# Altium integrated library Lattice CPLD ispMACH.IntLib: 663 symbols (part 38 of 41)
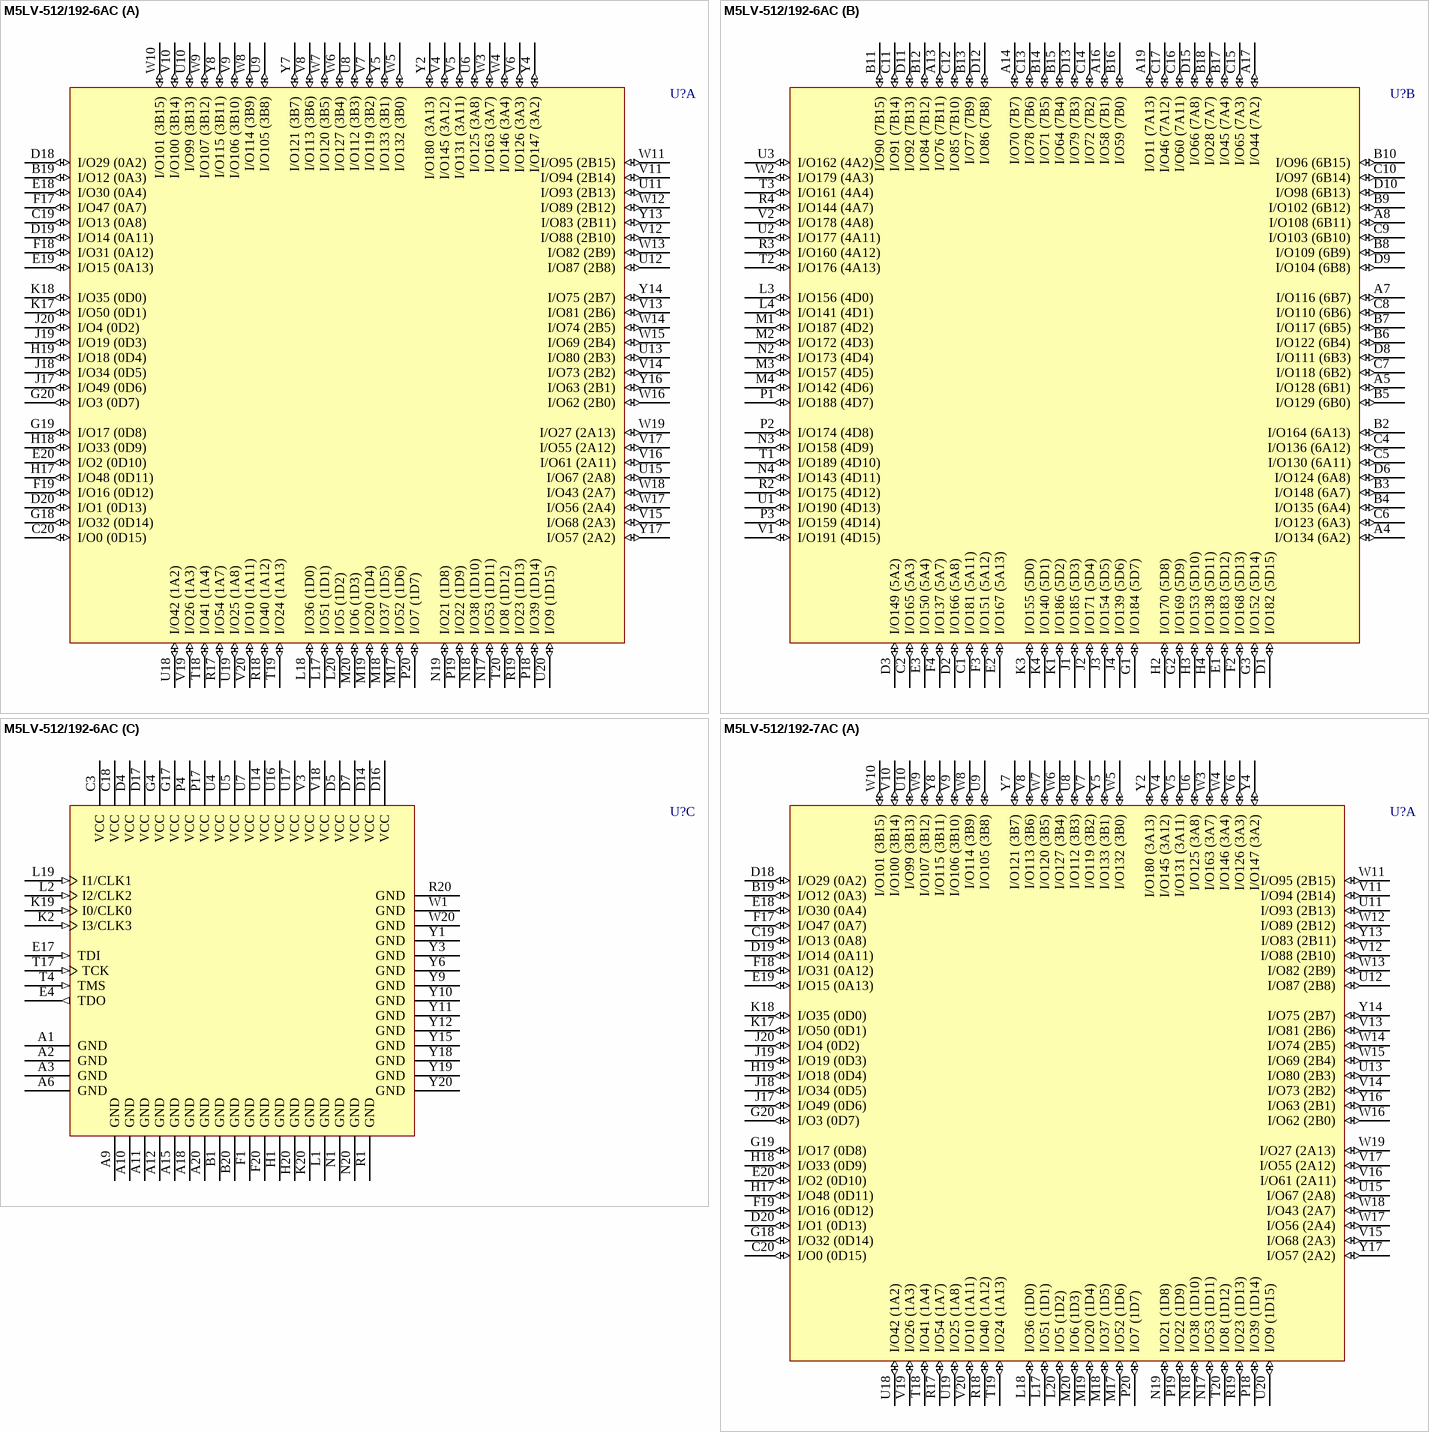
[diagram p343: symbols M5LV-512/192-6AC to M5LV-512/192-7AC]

## M5LV-512/192-6AC
designator U?
High-Density and High-I/O Complex PLD
footprint SBGA256 (BGA, 256-Leads, Body 27x27mm, Pitch 1.27mm)
3D model M5LV-SBGA256 (256-Ball Super Ball Grid Array (SBGA256))
part A pins: B19 I/O12 (0A3) (io), C19 I/O13 (0A8) (io), C20 I/O0 (0D15) (io), D18 I/O29 (0A2) (io), D19 I/O14 (0A11) (io), D20 I/O1 (0D13) (io), E18 I/O30 (0A4) (io), E19 I/O15 (0A13) (io), E20 I/O2 (0D10) (io), F17 I/O47 (0A7) (io), F18 I/O31 (0A12) (io), F19 I/O16 (0D12) (io), G18 I/O32 (0D14) (io), G19 I/O17 (0D8) (io), G20 I/O3 (0D7) (io), H17 I/O48 (0D11) (io), H18 I/O33 (0D9) (io), H19 I/O18 (0D4) (io), J17 I/O49 (0D6) (io), J18 I/O34 (0D5) (io), J19 I/O19 (0D3) (io), J20 I/O4 (0D2) (io), K17 I/O50 (0D1) (io), K18 I/O35 (0D0) (io), L17 I/O51 (1D1) (io), L18 I/O36 (1D0) (io), L20 I/O5 (1D2) (io), M17 I/O52 (1D6) (io), M18 I/O37 (1D5) (io), M19 I/O20 (1D4) (io), M20 I/O6 (1D3) (io), N17 I/O53 (1D11) (io), N18 I/O38 (1D10) (io), N19 I/O21 (1D8) (io), P18 I/O39 (1D14) (io), P19 I/O22 (1D9) (io), P20 I/O7 (1D7) (io), R17 I/O54 (1A7) (io), R18 I/O40 (1A12) (io), R19 I/O23 (1D13) (io), T18 I/O41 (1A4) (io), T19 I/O24 (1A13) (io), T20 I/O8 (1D12) (io), U6 I/O125 (3A8) (io), U8 I/O112 (3B3) (io), U9 I/O105 (3B8) (io), U10 I/O99 (3B13) (io), U11 I/O93 (2B13) (io), U12 I/O87 (2B8) (io), U13 I/O80 (2B3) (io), U15 I/O67 (2A8) (io), U18 I/O42 (1A2) (io), U19 I/O25 (1A8) (io), U20 I/O9 (1D15) (io), V4 I/O145 (3A12) (io), V5 I/O131 (3A11) (io), V6 I/O126 (3A3) (io), V7 I/O119 (3B2) (io), V8 I/O113 (3B6) (io), V9 I/O106 (3B10) (io), V10 I/O100 (3B14) (io), V11 I/O94 (2B14) (io), V12 I/O88 (2B10) (io), V13 I/O81 (2B6) (io), V14 I/O73 (2B2) (io), V15 I/O68 (2A3) (io), V16 I/O61 (2A11) (io), V17 I/O55 (2A12) (io), V19 I/O26 (1A3) (io), V20 I/O10 (1A11) (io), W3 I/O163 (3A7) (io), W4 I/O146 (3A4) (io), W5 I/O132 (3B0) (io), W6 I/O127 (3B4) (io), W7 I/O120 (3B5) (io), W8 I/O114 (3B9) (io), W9 I/O107 (3B12) (io), W10 I/O101 (3B15) (io), W11 I/O95 (2B15) (io), W12 I/O89 (2B12) (io), W13 I/O82 (2B9) (io), W14 I/O74 (2B5) (io), W15 I/O69 (2B4) (io), W16 I/O62 (2B0) (io), W17 I/O56 (2A4) (io), W18 I/O43 (2A7) (io), W19 I/O27 (2A13) (io), Y2 I/O180 (3A13) (io), Y4 I/O147 (3A2) (io), Y5 I/O133 (3B1) (io), Y7 I/O121 (3B7) (io), Y8 I/O115 (3B11) (io), Y13 I/O83 (2B11) (io), Y14 I/O75 (2B7) (io), Y16 I/O63 (2B1) (io), Y17 I/O57 (2A2) (io)
part B pins: A4 I/O134 (6A2) (io), A5 I/O128 (6B1) (io), A7 I/O116 (6B7) (io), A8 I/O108 (6B11) (io), A13 I/O76 (7B11) (io), A14 I/O70 (7B7) (io), A16 I/O58 (7B1) (io), A17 I/O44 (7A2) (io), A19 I/O11 (7A13) (io), B2 I/O164 (6A13) (io), B3 I/O148 (6A7) (io), B4 I/O135 (6A4) (io), B5 I/O129 (6B0) (io), B6 I/O122 (6B4) (io), B7 I/O117 (6B5) (io), B8 I/O109 (6B9) (io), B9 I/O102 (6B12) (io), B10 I/O96 (6B15) (io), B11 I/O90 (7B15) (io), B12 I/O84 (7B12) (io), B13 I/O77 (7B9) (io), B14 I/O71 (7B5) (io), B15 I/O64 (7B4) (io), B16 I/O59 (7B0) (io), B17 I/O45 (7A4) (io), B18 I/O28 (7A7) (io), C1 I/O181 (5A11) (io), C2 I/O165 (5A3) (io), C4 I/O136 (6A12) (io), C5 I/O130 (6A11) (io), C6 I/O123 (6A3) (io), C7 I/O118 (6B2) (io), C8 I/O110 (6B6) (io), C9 I/O103 (6B10) (io), C10 I/O97 (6B14) (io), C11 I/O91 (7B14) (io), C12 I/O85 (7B10) (io), C13 I/O78 (7B6) (io), C14 I/O72 (7B2) (io), C15 I/O65 (7A3) (io), C16 I/O60 (7A11) (io), C17 I/O46 (7A12) (io), D1 I/O182 (5D15) (io), D2 I/O166 (5A8) (io), D3 I/O149 (5A2) (io), D6 I/O124 (6A8) (io), D8 I/O111 (6B3) (io), D9 I/O104 (6B8) (io), D10 I/O98 (6B13) (io), D11 I/O92 (7B13) (io), D12 I/O86 (7B8) (io), D13 I/O79 (7B3) (io), D15 I/O66 (7A8) (io), E1 I/O183 (5D12) (io), E2 I/O167 (5A13) (io), E3 I/O150 (5A4) (io), F2 I/O168 (5D13) (io), F3 I/O151 (5A12) (io), F4 I/O137 (5A7) (io), G1 I/O184 (5D7) (io), G2 I/O169 (5D9) (io), G3 I/O152 (5D14) (io), H2 I/O170 (5D8) (io), H3 I/O153 (5D10) (io), H4 I/O138 (5D11) (io), J1 I/O185 (5D3) (io), J2 I/O171 (5D4) (io), J3 I/O154 (5D5) (io), J4 I/O139 (5D6) (io), K1 I/O186 (5D2) (io), K3 I/O155 (5D0) (io), K4 I/O140 (5D1) (io), L3 I/O156 (4D0) (io), L4 I/O141 (4D1) (io), M1 I/O187 (4D2) (io), M2 I/O172 (4D3) (io), M3 I/O157 (4D5) (io), M4 I/O142 (4D6) (io), N2 I/O173 (4D4) (io), N3 I/O158 (4D9) (io), N4 I/O143 (4D11) (io), P1 I/O188 (4D7) (io), P2 I/O174 (4D8) (io), P3 I/O159 (4D14) (io), R2 I/O175 (4D12) (io), R3 I/O160 (4A12) (io), R4 I/O144 (4A7) (io), T1 I/O189 (4D10) (io), T2 I/O176 (4A13) (io), T3 I/O161 (4A4) (io), U1 I/O190 (4D13) (io), U2 I/O177 (4A11) (io), U3 I/O162 (4A2) (io), V1 I/O191 (4D15) (io), V2 I/O178 (4A8) (io), W2 I/O179 (4A3) (io)
part C pins: A1 GND (power), A2 GND (power), A3 GND (power), A6 GND (power), A9 GND (power), A10 GND (power), A11 GND (power), A12 GND (power), A15 GND (power), A18 GND (power), A20 GND (power), B1 GND (power), B20 GND (power), C3 VCC (power), C18 VCC (power), D4 VCC (power), D5 VCC (power), D7 VCC (power), D14 VCC (power), D16 VCC (power), D17 VCC (power), E4 TDO (out), E17 TDI (in), F1 GND (power), F20 GND (power), G4 VCC (power), G17 VCC (power), H1 GND (power), H20 GND (power), K2 I3/CLK3 (in), K19 I0/CLK0 (in), K20 GND (power), L1 GND (power), L2 I2/CLK2 (in), L19 I1/CLK1 (in), N1 GND (power), N20 GND (power), P4 VCC (power), P17 VCC (power), R1 GND (power), R20 GND (power), T4 TMS (in), T17 TCK (in), U4 VCC (power), U5 VCC (power), U7 VCC (power), U14 VCC (power), U16 VCC (power), U17 VCC (power), V3 VCC (power), V18 VCC (power), W1 GND (power), W20 GND (power), Y1 GND (power), Y3 GND (power), Y6 GND (power), Y9 GND (power), Y10 GND (power), Y11 GND (power), Y12 GND (power), Y15 GND (power), Y18 GND (power), Y19 GND (power), Y20 GND (power)

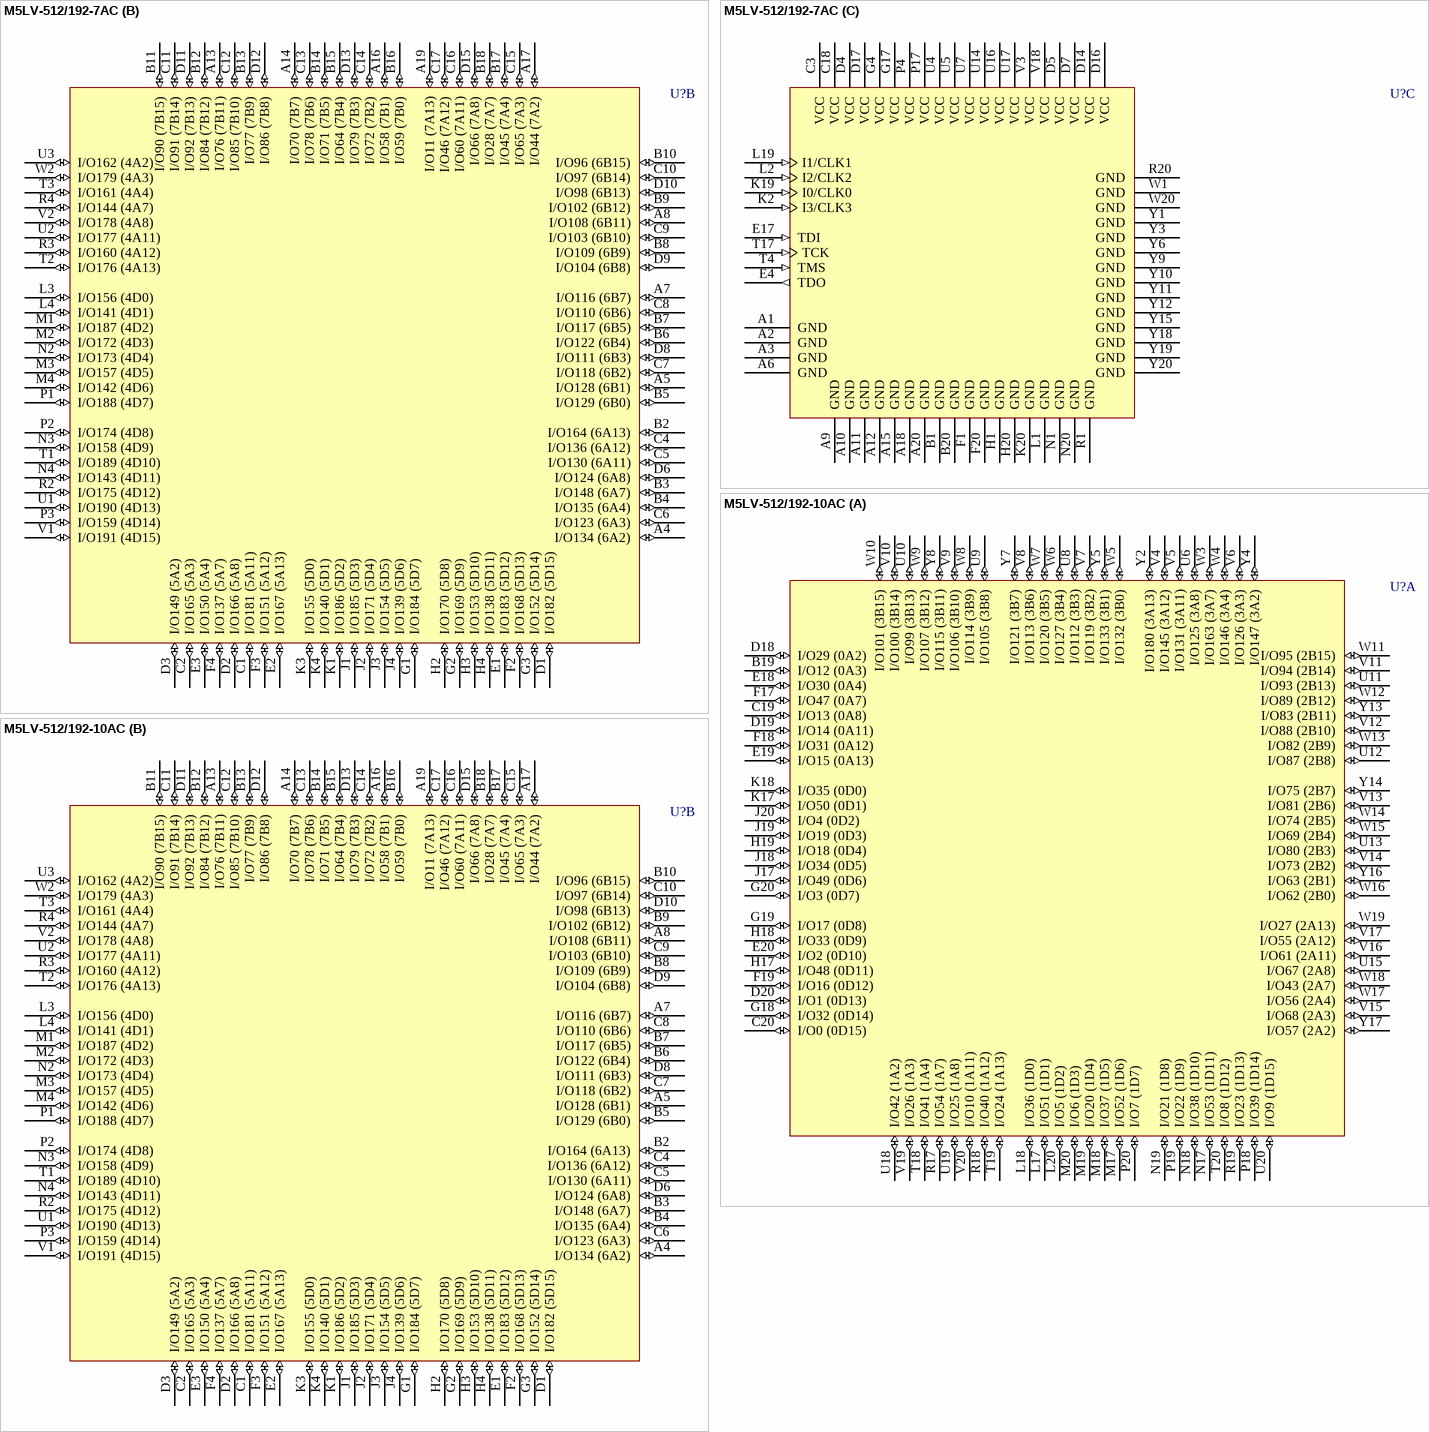
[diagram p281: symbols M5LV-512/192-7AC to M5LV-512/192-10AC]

## M5LV-512/192-7AC
designator U?
High-Density and High-I/O Complex PLD
footprint SBGA256 (BGA, 256-Leads, Body 27x27mm, Pitch 1.27mm)
3D model M5LV-SBGA256 (256-Ball Super Ball Grid Array (SBGA256))
part A pins: B19 I/O12 (0A3) (io), C19 I/O13 (0A8) (io), C20 I/O0 (0D15) (io), D18 I/O29 (0A2) (io), D19 I/O14 (0A11) (io), D20 I/O1 (0D13) (io), E18 I/O30 (0A4) (io), E19 I/O15 (0A13) (io), E20 I/O2 (0D10) (io), F17 I/O47 (0A7) (io), F18 I/O31 (0A12) (io), F19 I/O16 (0D12) (io), G18 I/O32 (0D14) (io), G19 I/O17 (0D8) (io), G20 I/O3 (0D7) (io), H17 I/O48 (0D11) (io), H18 I/O33 (0D9) (io), H19 I/O18 (0D4) (io), J17 I/O49 (0D6) (io), J18 I/O34 (0D5) (io), J19 I/O19 (0D3) (io), J20 I/O4 (0D2) (io), K17 I/O50 (0D1) (io), K18 I/O35 (0D0) (io), L17 I/O51 (1D1) (io), L18 I/O36 (1D0) (io), L20 I/O5 (1D2) (io), M17 I/O52 (1D6) (io), M18 I/O37 (1D5) (io), M19 I/O20 (1D4) (io), M20 I/O6 (1D3) (io), N17 I/O53 (1D11) (io), N18 I/O38 (1D10) (io), N19 I/O21 (1D8) (io), P18 I/O39 (1D14) (io), P19 I/O22 (1D9) (io), P20 I/O7 (1D7) (io), R17 I/O54 (1A7) (io), R18 I/O40 (1A12) (io), R19 I/O23 (1D13) (io), T18 I/O41 (1A4) (io), T19 I/O24 (1A13) (io), T20 I/O8 (1D12) (io), U6 I/O125 (3A8) (io), U8 I/O112 (3B3) (io), U9 I/O105 (3B8) (io), U10 I/O99 (3B13) (io), U11 I/O93 (2B13) (io), U12 I/O87 (2B8) (io), U13 I/O80 (2B3) (io), U15 I/O67 (2A8) (io), U18 I/O42 (1A2) (io), U19 I/O25 (1A8) (io), U20 I/O9 (1D15) (io), V4 I/O145 (3A12) (io), V5 I/O131 (3A11) (io), V6 I/O126 (3A3) (io), V7 I/O119 (3B2) (io), V8 I/O113 (3B6) (io), V9 I/O106 (3B10) (io), V10 I/O100 (3B14) (io), V11 I/O94 (2B14) (io), V12 I/O88 (2B10) (io), V13 I/O81 (2B6) (io), V14 I/O73 (2B2) (io), V15 I/O68 (2A3) (io), V16 I/O61 (2A11) (io), V17 I/O55 (2A12) (io), V19 I/O26 (1A3) (io), V20 I/O10 (1A11) (io), W3 I/O163 (3A7) (io), W4 I/O146 (3A4) (io), W5 I/O132 (3B0) (io), W6 I/O127 (3B4) (io), W7 I/O120 (3B5) (io), W8 I/O114 (3B9) (io), W9 I/O107 (3B12) (io), W10 I/O101 (3B15) (io), W11 I/O95 (2B15) (io), W12 I/O89 (2B12) (io), W13 I/O82 (2B9) (io), W14 I/O74 (2B5) (io), W15 I/O69 (2B4) (io), W16 I/O62 (2B0) (io), W17 I/O56 (2A4) (io), W18 I/O43 (2A7) (io), W19 I/O27 (2A13) (io), Y2 I/O180 (3A13) (io), Y4 I/O147 (3A2) (io), Y5 I/O133 (3B1) (io), Y7 I/O121 (3B7) (io), Y8 I/O115 (3B11) (io), Y13 I/O83 (2B11) (io), Y14 I/O75 (2B7) (io), Y16 I/O63 (2B1) (io), Y17 I/O57 (2A2) (io)
part B pins: A4 I/O134 (6A2) (io), A5 I/O128 (6B1) (io), A7 I/O116 (6B7) (io), A8 I/O108 (6B11) (io), A13 I/O76 (7B11) (io), A14 I/O70 (7B7) (io), A16 I/O58 (7B1) (io), A17 I/O44 (7A2) (io), A19 I/O11 (7A13) (io), B2 I/O164 (6A13) (io), B3 I/O148 (6A7) (io), B4 I/O135 (6A4) (io), B5 I/O129 (6B0) (io), B6 I/O122 (6B4) (io), B7 I/O117 (6B5) (io), B8 I/O109 (6B9) (io), B9 I/O102 (6B12) (io), B10 I/O96 (6B15) (io), B11 I/O90 (7B15) (io), B12 I/O84 (7B12) (io), B13 I/O77 (7B9) (io), B14 I/O71 (7B5) (io), B15 I/O64 (7B4) (io), B16 I/O59 (7B0) (io), B17 I/O45 (7A4) (io), B18 I/O28 (7A7) (io), C1 I/O181 (5A11) (io), C2 I/O165 (5A3) (io), C4 I/O136 (6A12) (io), C5 I/O130 (6A11) (io), C6 I/O123 (6A3) (io), C7 I/O118 (6B2) (io), C8 I/O110 (6B6) (io), C9 I/O103 (6B10) (io), C10 I/O97 (6B14) (io), C11 I/O91 (7B14) (io), C12 I/O85 (7B10) (io), C13 I/O78 (7B6) (io), C14 I/O72 (7B2) (io), C15 I/O65 (7A3) (io), C16 I/O60 (7A11) (io), C17 I/O46 (7A12) (io), D1 I/O182 (5D15) (io), D2 I/O166 (5A8) (io), D3 I/O149 (5A2) (io), D6 I/O124 (6A8) (io), D8 I/O111 (6B3) (io), D9 I/O104 (6B8) (io), D10 I/O98 (6B13) (io), D11 I/O92 (7B13) (io), D12 I/O86 (7B8) (io), D13 I/O79 (7B3) (io), D15 I/O66 (7A8) (io), E1 I/O183 (5D12) (io), E2 I/O167 (5A13) (io), E3 I/O150 (5A4) (io), F2 I/O168 (5D13) (io), F3 I/O151 (5A12) (io), F4 I/O137 (5A7) (io), G1 I/O184 (5D7) (io), G2 I/O169 (5D9) (io), G3 I/O152 (5D14) (io), H2 I/O170 (5D8) (io), H3 I/O153 (5D10) (io), H4 I/O138 (5D11) (io), J1 I/O185 (5D3) (io), J2 I/O171 (5D4) (io), J3 I/O154 (5D5) (io), J4 I/O139 (5D6) (io), K1 I/O186 (5D2) (io), K3 I/O155 (5D0) (io), K4 I/O140 (5D1) (io), L3 I/O156 (4D0) (io), L4 I/O141 (4D1) (io), M1 I/O187 (4D2) (io), M2 I/O172 (4D3) (io), M3 I/O157 (4D5) (io), M4 I/O142 (4D6) (io), N2 I/O173 (4D4) (io), N3 I/O158 (4D9) (io), N4 I/O143 (4D11) (io), P1 I/O188 (4D7) (io), P2 I/O174 (4D8) (io), P3 I/O159 (4D14) (io), R2 I/O175 (4D12) (io), R3 I/O160 (4A12) (io), R4 I/O144 (4A7) (io), T1 I/O189 (4D10) (io), T2 I/O176 (4A13) (io), T3 I/O161 (4A4) (io), U1 I/O190 (4D13) (io), U2 I/O177 (4A11) (io), U3 I/O162 (4A2) (io), V1 I/O191 (4D15) (io), V2 I/O178 (4A8) (io), W2 I/O179 (4A3) (io)
part C pins: A1 GND (power), A2 GND (power), A3 GND (power), A6 GND (power), A9 GND (power), A10 GND (power), A11 GND (power), A12 GND (power), A15 GND (power), A18 GND (power), A20 GND (power), B1 GND (power), B20 GND (power), C3 VCC (power), C18 VCC (power), D4 VCC (power), D5 VCC (power), D7 VCC (power), D14 VCC (power), D16 VCC (power), D17 VCC (power), E4 TDO (out), E17 TDI (in), F1 GND (power), F20 GND (power), G4 VCC (power), G17 VCC (power), H1 GND (power), H20 GND (power), K2 I3/CLK3 (in), K19 I0/CLK0 (in), K20 GND (power), L1 GND (power), L2 I2/CLK2 (in), L19 I1/CLK1 (in), N1 GND (power), N20 GND (power), P4 VCC (power), P17 VCC (power), R1 GND (power), R20 GND (power), T4 TMS (in), T17 TCK (in), U4 VCC (power), U5 VCC (power), U7 VCC (power), U14 VCC (power), U16 VCC (power), U17 VCC (power), V3 VCC (power), V18 VCC (power), W1 GND (power), W20 GND (power), Y1 GND (power), Y3 GND (power), Y6 GND (power), Y9 GND (power), Y10 GND (power), Y11 GND (power), Y12 GND (power), Y15 GND (power), Y18 GND (power), Y19 GND (power), Y20 GND (power)

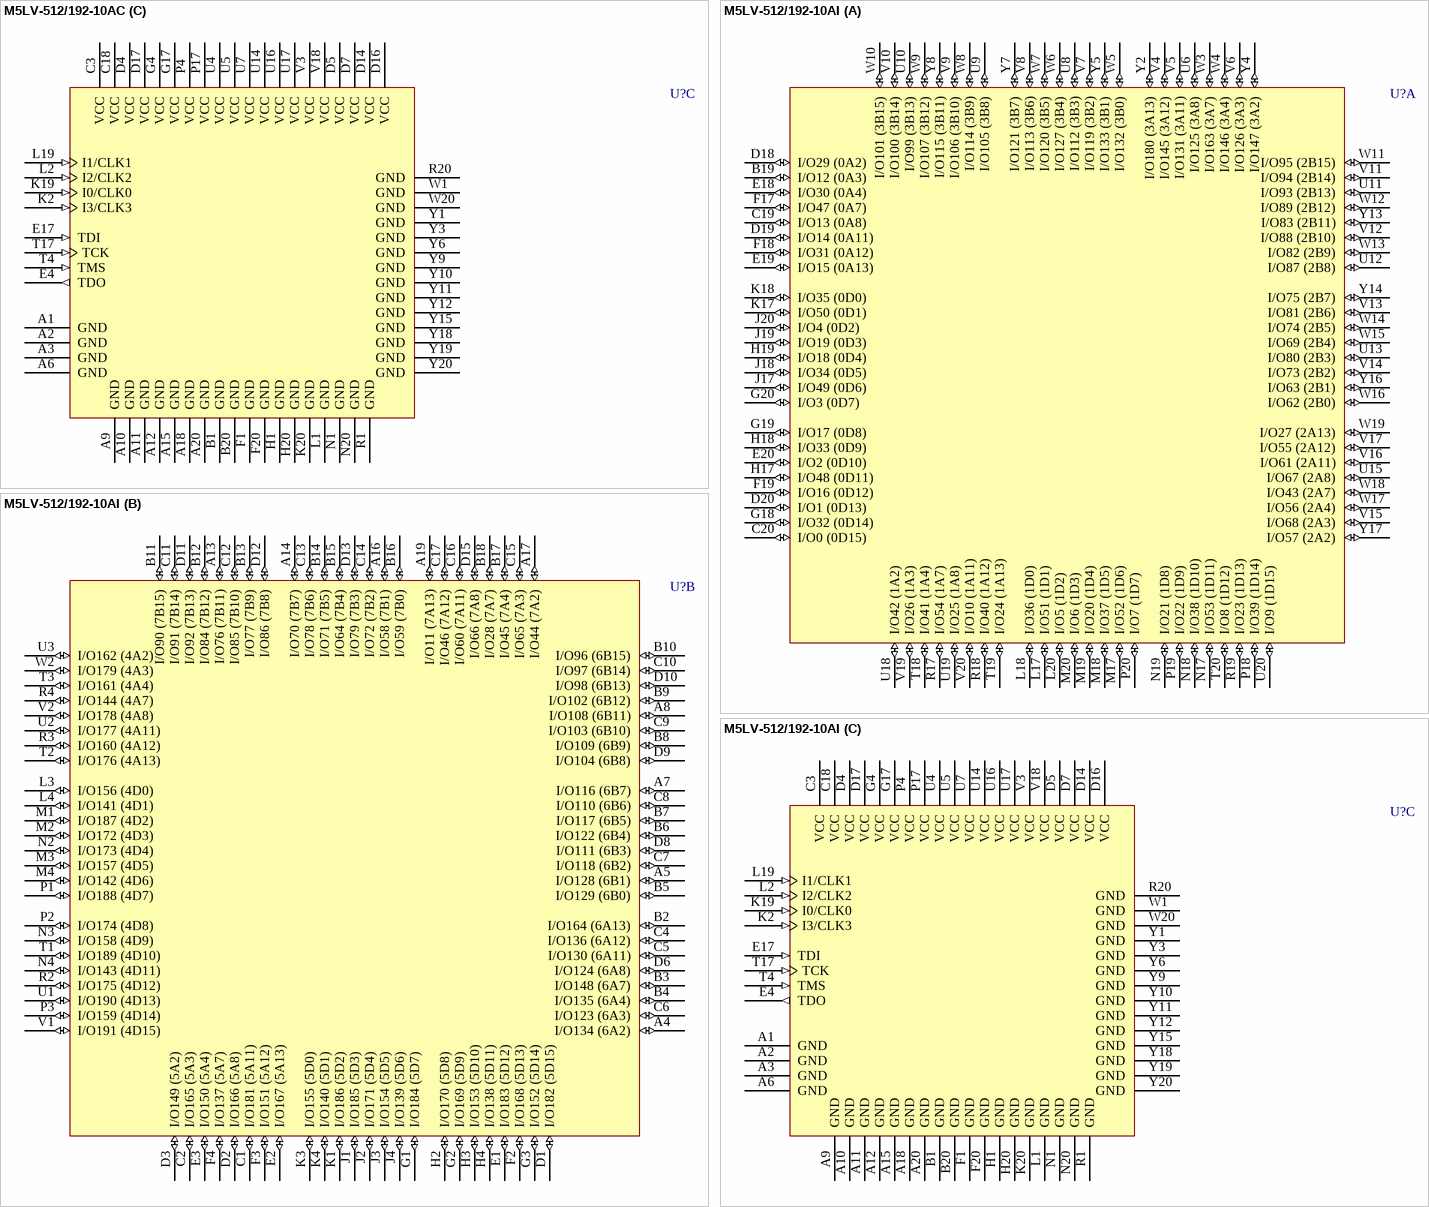
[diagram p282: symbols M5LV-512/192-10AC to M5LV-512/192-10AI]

## M5LV-512/192-10AC
designator U?
High-Density and High-I/O Complex PLD
footprint SBGA256 (BGA, 256-Leads, Body 27x27mm, Pitch 1.27mm)
3D model M5LV-SBGA256 (256-Ball Super Ball Grid Array (SBGA256))
part A pins: B19 I/O12 (0A3) (io), C19 I/O13 (0A8) (io), C20 I/O0 (0D15) (io), D18 I/O29 (0A2) (io), D19 I/O14 (0A11) (io), D20 I/O1 (0D13) (io), E18 I/O30 (0A4) (io), E19 I/O15 (0A13) (io), E20 I/O2 (0D10) (io), F17 I/O47 (0A7) (io), F18 I/O31 (0A12) (io), F19 I/O16 (0D12) (io), G18 I/O32 (0D14) (io), G19 I/O17 (0D8) (io), G20 I/O3 (0D7) (io), H17 I/O48 (0D11) (io), H18 I/O33 (0D9) (io), H19 I/O18 (0D4) (io), J17 I/O49 (0D6) (io), J18 I/O34 (0D5) (io), J19 I/O19 (0D3) (io), J20 I/O4 (0D2) (io), K17 I/O50 (0D1) (io), K18 I/O35 (0D0) (io), L17 I/O51 (1D1) (io), L18 I/O36 (1D0) (io), L20 I/O5 (1D2) (io), M17 I/O52 (1D6) (io), M18 I/O37 (1D5) (io), M19 I/O20 (1D4) (io), M20 I/O6 (1D3) (io), N17 I/O53 (1D11) (io), N18 I/O38 (1D10) (io), N19 I/O21 (1D8) (io), P18 I/O39 (1D14) (io), P19 I/O22 (1D9) (io), P20 I/O7 (1D7) (io), R17 I/O54 (1A7) (io), R18 I/O40 (1A12) (io), R19 I/O23 (1D13) (io), T18 I/O41 (1A4) (io), T19 I/O24 (1A13) (io), T20 I/O8 (1D12) (io), U6 I/O125 (3A8) (io), U8 I/O112 (3B3) (io), U9 I/O105 (3B8) (io), U10 I/O99 (3B13) (io), U11 I/O93 (2B13) (io), U12 I/O87 (2B8) (io), U13 I/O80 (2B3) (io), U15 I/O67 (2A8) (io), U18 I/O42 (1A2) (io), U19 I/O25 (1A8) (io), U20 I/O9 (1D15) (io), V4 I/O145 (3A12) (io), V5 I/O131 (3A11) (io), V6 I/O126 (3A3) (io), V7 I/O119 (3B2) (io), V8 I/O113 (3B6) (io), V9 I/O106 (3B10) (io), V10 I/O100 (3B14) (io), V11 I/O94 (2B14) (io), V12 I/O88 (2B10) (io), V13 I/O81 (2B6) (io), V14 I/O73 (2B2) (io), V15 I/O68 (2A3) (io), V16 I/O61 (2A11) (io), V17 I/O55 (2A12) (io), V19 I/O26 (1A3) (io), V20 I/O10 (1A11) (io), W3 I/O163 (3A7) (io), W4 I/O146 (3A4) (io), W5 I/O132 (3B0) (io), W6 I/O127 (3B4) (io), W7 I/O120 (3B5) (io), W8 I/O114 (3B9) (io), W9 I/O107 (3B12) (io), W10 I/O101 (3B15) (io), W11 I/O95 (2B15) (io), W12 I/O89 (2B12) (io), W13 I/O82 (2B9) (io), W14 I/O74 (2B5) (io), W15 I/O69 (2B4) (io), W16 I/O62 (2B0) (io), W17 I/O56 (2A4) (io), W18 I/O43 (2A7) (io), W19 I/O27 (2A13) (io), Y2 I/O180 (3A13) (io), Y4 I/O147 (3A2) (io), Y5 I/O133 (3B1) (io), Y7 I/O121 (3B7) (io), Y8 I/O115 (3B11) (io), Y13 I/O83 (2B11) (io), Y14 I/O75 (2B7) (io), Y16 I/O63 (2B1) (io), Y17 I/O57 (2A2) (io)
part B pins: A4 I/O134 (6A2) (io), A5 I/O128 (6B1) (io), A7 I/O116 (6B7) (io), A8 I/O108 (6B11) (io), A13 I/O76 (7B11) (io), A14 I/O70 (7B7) (io), A16 I/O58 (7B1) (io), A17 I/O44 (7A2) (io), A19 I/O11 (7A13) (io), B2 I/O164 (6A13) (io), B3 I/O148 (6A7) (io), B4 I/O135 (6A4) (io), B5 I/O129 (6B0) (io), B6 I/O122 (6B4) (io), B7 I/O117 (6B5) (io), B8 I/O109 (6B9) (io), B9 I/O102 (6B12) (io), B10 I/O96 (6B15) (io), B11 I/O90 (7B15) (io), B12 I/O84 (7B12) (io), B13 I/O77 (7B9) (io), B14 I/O71 (7B5) (io), B15 I/O64 (7B4) (io), B16 I/O59 (7B0) (io), B17 I/O45 (7A4) (io), B18 I/O28 (7A7) (io), C1 I/O181 (5A11) (io), C2 I/O165 (5A3) (io), C4 I/O136 (6A12) (io), C5 I/O130 (6A11) (io), C6 I/O123 (6A3) (io), C7 I/O118 (6B2) (io), C8 I/O110 (6B6) (io), C9 I/O103 (6B10) (io), C10 I/O97 (6B14) (io), C11 I/O91 (7B14) (io), C12 I/O85 (7B10) (io), C13 I/O78 (7B6) (io), C14 I/O72 (7B2) (io), C15 I/O65 (7A3) (io), C16 I/O60 (7A11) (io), C17 I/O46 (7A12) (io), D1 I/O182 (5D15) (io), D2 I/O166 (5A8) (io), D3 I/O149 (5A2) (io), D6 I/O124 (6A8) (io), D8 I/O111 (6B3) (io), D9 I/O104 (6B8) (io), D10 I/O98 (6B13) (io), D11 I/O92 (7B13) (io), D12 I/O86 (7B8) (io), D13 I/O79 (7B3) (io), D15 I/O66 (7A8) (io), E1 I/O183 (5D12) (io), E2 I/O167 (5A13) (io), E3 I/O150 (5A4) (io), F2 I/O168 (5D13) (io), F3 I/O151 (5A12) (io), F4 I/O137 (5A7) (io), G1 I/O184 (5D7) (io), G2 I/O169 (5D9) (io), G3 I/O152 (5D14) (io), H2 I/O170 (5D8) (io), H3 I/O153 (5D10) (io), H4 I/O138 (5D11) (io), J1 I/O185 (5D3) (io), J2 I/O171 (5D4) (io), J3 I/O154 (5D5) (io), J4 I/O139 (5D6) (io), K1 I/O186 (5D2) (io), K3 I/O155 (5D0) (io), K4 I/O140 (5D1) (io), L3 I/O156 (4D0) (io), L4 I/O141 (4D1) (io), M1 I/O187 (4D2) (io), M2 I/O172 (4D3) (io), M3 I/O157 (4D5) (io), M4 I/O142 (4D6) (io), N2 I/O173 (4D4) (io), N3 I/O158 (4D9) (io), N4 I/O143 (4D11) (io), P1 I/O188 (4D7) (io), P2 I/O174 (4D8) (io), P3 I/O159 (4D14) (io), R2 I/O175 (4D12) (io), R3 I/O160 (4A12) (io), R4 I/O144 (4A7) (io), T1 I/O189 (4D10) (io), T2 I/O176 (4A13) (io), T3 I/O161 (4A4) (io), U1 I/O190 (4D13) (io), U2 I/O177 (4A11) (io), U3 I/O162 (4A2) (io), V1 I/O191 (4D15) (io), V2 I/O178 (4A8) (io), W2 I/O179 (4A3) (io)
part C pins: A1 GND (power), A2 GND (power), A3 GND (power), A6 GND (power), A9 GND (power), A10 GND (power), A11 GND (power), A12 GND (power), A15 GND (power), A18 GND (power), A20 GND (power), B1 GND (power), B20 GND (power), C3 VCC (power), C18 VCC (power), D4 VCC (power), D5 VCC (power), D7 VCC (power), D14 VCC (power), D16 VCC (power), D17 VCC (power), E4 TDO (out), E17 TDI (in), F1 GND (power), F20 GND (power), G4 VCC (power), G17 VCC (power), H1 GND (power), H20 GND (power), K2 I3/CLK3 (in), K19 I0/CLK0 (in), K20 GND (power), L1 GND (power), L2 I2/CLK2 (in), L19 I1/CLK1 (in), N1 GND (power), N20 GND (power), P4 VCC (power), P17 VCC (power), R1 GND (power), R20 GND (power), T4 TMS (in), T17 TCK (in), U4 VCC (power), U5 VCC (power), U7 VCC (power), U14 VCC (power), U16 VCC (power), U17 VCC (power), V3 VCC (power), V18 VCC (power), W1 GND (power), W20 GND (power), Y1 GND (power), Y3 GND (power), Y6 GND (power), Y9 GND (power), Y10 GND (power), Y11 GND (power), Y12 GND (power), Y15 GND (power), Y18 GND (power), Y19 GND (power), Y20 GND (power)

## M5LV-512/192-10AI
designator U?
High-Density and High-I/O Complex PLD
footprint SBGA256 (BGA, 256-Leads, Body 27x27mm, Pitch 1.27mm)
3D model M5LV-SBGA256 (256-Ball Super Ball Grid Array (SBGA256))
part A pins: B19 I/O12 (0A3) (io), C19 I/O13 (0A8) (io), C20 I/O0 (0D15) (io), D18 I/O29 (0A2) (io), D19 I/O14 (0A11) (io), D20 I/O1 (0D13) (io), E18 I/O30 (0A4) (io), E19 I/O15 (0A13) (io), E20 I/O2 (0D10) (io), F17 I/O47 (0A7) (io), F18 I/O31 (0A12) (io), F19 I/O16 (0D12) (io), G18 I/O32 (0D14) (io), G19 I/O17 (0D8) (io), G20 I/O3 (0D7) (io), H17 I/O48 (0D11) (io), H18 I/O33 (0D9) (io), H19 I/O18 (0D4) (io), J17 I/O49 (0D6) (io), J18 I/O34 (0D5) (io), J19 I/O19 (0D3) (io), J20 I/O4 (0D2) (io), K17 I/O50 (0D1) (io), K18 I/O35 (0D0) (io), L17 I/O51 (1D1) (io), L18 I/O36 (1D0) (io), L20 I/O5 (1D2) (io), M17 I/O52 (1D6) (io), M18 I/O37 (1D5) (io), M19 I/O20 (1D4) (io), M20 I/O6 (1D3) (io), N17 I/O53 (1D11) (io), N18 I/O38 (1D10) (io), N19 I/O21 (1D8) (io), P18 I/O39 (1D14) (io), P19 I/O22 (1D9) (io), P20 I/O7 (1D7) (io), R17 I/O54 (1A7) (io), R18 I/O40 (1A12) (io), R19 I/O23 (1D13) (io), T18 I/O41 (1A4) (io), T19 I/O24 (1A13) (io), T20 I/O8 (1D12) (io), U6 I/O125 (3A8) (io), U8 I/O112 (3B3) (io), U9 I/O105 (3B8) (io), U10 I/O99 (3B13) (io), U11 I/O93 (2B13) (io), U12 I/O87 (2B8) (io), U13 I/O80 (2B3) (io), U15 I/O67 (2A8) (io), U18 I/O42 (1A2) (io), U19 I/O25 (1A8) (io), U20 I/O9 (1D15) (io), V4 I/O145 (3A12) (io), V5 I/O131 (3A11) (io), V6 I/O126 (3A3) (io), V7 I/O119 (3B2) (io), V8 I/O113 (3B6) (io), V9 I/O106 (3B10) (io), V10 I/O100 (3B14) (io), V11 I/O94 (2B14) (io), V12 I/O88 (2B10) (io), V13 I/O81 (2B6) (io), V14 I/O73 (2B2) (io), V15 I/O68 (2A3) (io), V16 I/O61 (2A11) (io), V17 I/O55 (2A12) (io), V19 I/O26 (1A3) (io), V20 I/O10 (1A11) (io), W3 I/O163 (3A7) (io), W4 I/O146 (3A4) (io), W5 I/O132 (3B0) (io), W6 I/O127 (3B4) (io), W7 I/O120 (3B5) (io), W8 I/O114 (3B9) (io), W9 I/O107 (3B12) (io), W10 I/O101 (3B15) (io), W11 I/O95 (2B15) (io), W12 I/O89 (2B12) (io), W13 I/O82 (2B9) (io), W14 I/O74 (2B5) (io), W15 I/O69 (2B4) (io), W16 I/O62 (2B0) (io), W17 I/O56 (2A4) (io), W18 I/O43 (2A7) (io), W19 I/O27 (2A13) (io), Y2 I/O180 (3A13) (io), Y4 I/O147 (3A2) (io), Y5 I/O133 (3B1) (io), Y7 I/O121 (3B7) (io), Y8 I/O115 (3B11) (io), Y13 I/O83 (2B11) (io), Y14 I/O75 (2B7) (io), Y16 I/O63 (2B1) (io), Y17 I/O57 (2A2) (io)
part B pins: A4 I/O134 (6A2) (io), A5 I/O128 (6B1) (io), A7 I/O116 (6B7) (io), A8 I/O108 (6B11) (io), A13 I/O76 (7B11) (io), A14 I/O70 (7B7) (io), A16 I/O58 (7B1) (io), A17 I/O44 (7A2) (io), A19 I/O11 (7A13) (io), B2 I/O164 (6A13) (io), B3 I/O148 (6A7) (io), B4 I/O135 (6A4) (io), B5 I/O129 (6B0) (io), B6 I/O122 (6B4) (io), B7 I/O117 (6B5) (io), B8 I/O109 (6B9) (io), B9 I/O102 (6B12) (io), B10 I/O96 (6B15) (io), B11 I/O90 (7B15) (io), B12 I/O84 (7B12) (io), B13 I/O77 (7B9) (io), B14 I/O71 (7B5) (io), B15 I/O64 (7B4) (io), B16 I/O59 (7B0) (io), B17 I/O45 (7A4) (io), B18 I/O28 (7A7) (io), C1 I/O181 (5A11) (io), C2 I/O165 (5A3) (io), C4 I/O136 (6A12) (io), C5 I/O130 (6A11) (io), C6 I/O123 (6A3) (io), C7 I/O118 (6B2) (io), C8 I/O110 (6B6) (io), C9 I/O103 (6B10) (io), C10 I/O97 (6B14) (io), C11 I/O91 (7B14) (io), C12 I/O85 (7B10) (io), C13 I/O78 (7B6) (io), C14 I/O72 (7B2) (io), C15 I/O65 (7A3) (io), C16 I/O60 (7A11) (io), C17 I/O46 (7A12) (io), D1 I/O182 (5D15) (io), D2 I/O166 (5A8) (io), D3 I/O149 (5A2) (io), D6 I/O124 (6A8) (io), D8 I/O111 (6B3) (io), D9 I/O104 (6B8) (io), D10 I/O98 (6B13) (io), D11 I/O92 (7B13) (io), D12 I/O86 (7B8) (io), D13 I/O79 (7B3) (io), D15 I/O66 (7A8) (io), E1 I/O183 (5D12) (io), E2 I/O167 (5A13) (io), E3 I/O150 (5A4) (io), F2 I/O168 (5D13) (io), F3 I/O151 (5A12) (io), F4 I/O137 (5A7) (io), G1 I/O184 (5D7) (io), G2 I/O169 (5D9) (io), G3 I/O152 (5D14) (io), H2 I/O170 (5D8) (io), H3 I/O153 (5D10) (io), H4 I/O138 (5D11) (io), J1 I/O185 (5D3) (io), J2 I/O171 (5D4) (io), J3 I/O154 (5D5) (io), J4 I/O139 (5D6) (io), K1 I/O186 (5D2) (io), K3 I/O155 (5D0) (io), K4 I/O140 (5D1) (io), L3 I/O156 (4D0) (io), L4 I/O141 (4D1) (io), M1 I/O187 (4D2) (io), M2 I/O172 (4D3) (io), M3 I/O157 (4D5) (io), M4 I/O142 (4D6) (io), N2 I/O173 (4D4) (io), N3 I/O158 (4D9) (io), N4 I/O143 (4D11) (io), P1 I/O188 (4D7) (io), P2 I/O174 (4D8) (io), P3 I/O159 (4D14) (io), R2 I/O175 (4D12) (io), R3 I/O160 (4A12) (io), R4 I/O144 (4A7) (io), T1 I/O189 (4D10) (io), T2 I/O176 (4A13) (io), T3 I/O161 (4A4) (io), U1 I/O190 (4D13) (io), U2 I/O177 (4A11) (io), U3 I/O162 (4A2) (io), V1 I/O191 (4D15) (io), V2 I/O178 (4A8) (io), W2 I/O179 (4A3) (io)
part C pins: A1 GND (power), A2 GND (power), A3 GND (power), A6 GND (power), A9 GND (power), A10 GND (power), A11 GND (power), A12 GND (power), A15 GND (power), A18 GND (power), A20 GND (power), B1 GND (power), B20 GND (power), C3 VCC (power), C18 VCC (power), D4 VCC (power), D5 VCC (power), D7 VCC (power), D14 VCC (power), D16 VCC (power), D17 VCC (power), E4 TDO (out), E17 TDI (in), F1 GND (power), F20 GND (power), G4 VCC (power), G17 VCC (power), H1 GND (power), H20 GND (power), K2 I3/CLK3 (in), K19 I0/CLK0 (in), K20 GND (power), L1 GND (power), L2 I2/CLK2 (in), L19 I1/CLK1 (in), N1 GND (power), N20 GND (power), P4 VCC (power), P17 VCC (power), R1 GND (power), R20 GND (power), T4 TMS (in), T17 TCK (in), U4 VCC (power), U5 VCC (power), U7 VCC (power), U14 VCC (power), U16 VCC (power), U17 VCC (power), V3 VCC (power), V18 VCC (power), W1 GND (power), W20 GND (power), Y1 GND (power), Y3 GND (power), Y6 GND (power), Y9 GND (power), Y10 GND (power), Y11 GND (power), Y12 GND (power), Y15 GND (power), Y18 GND (power), Y19 GND (power), Y20 GND (power)

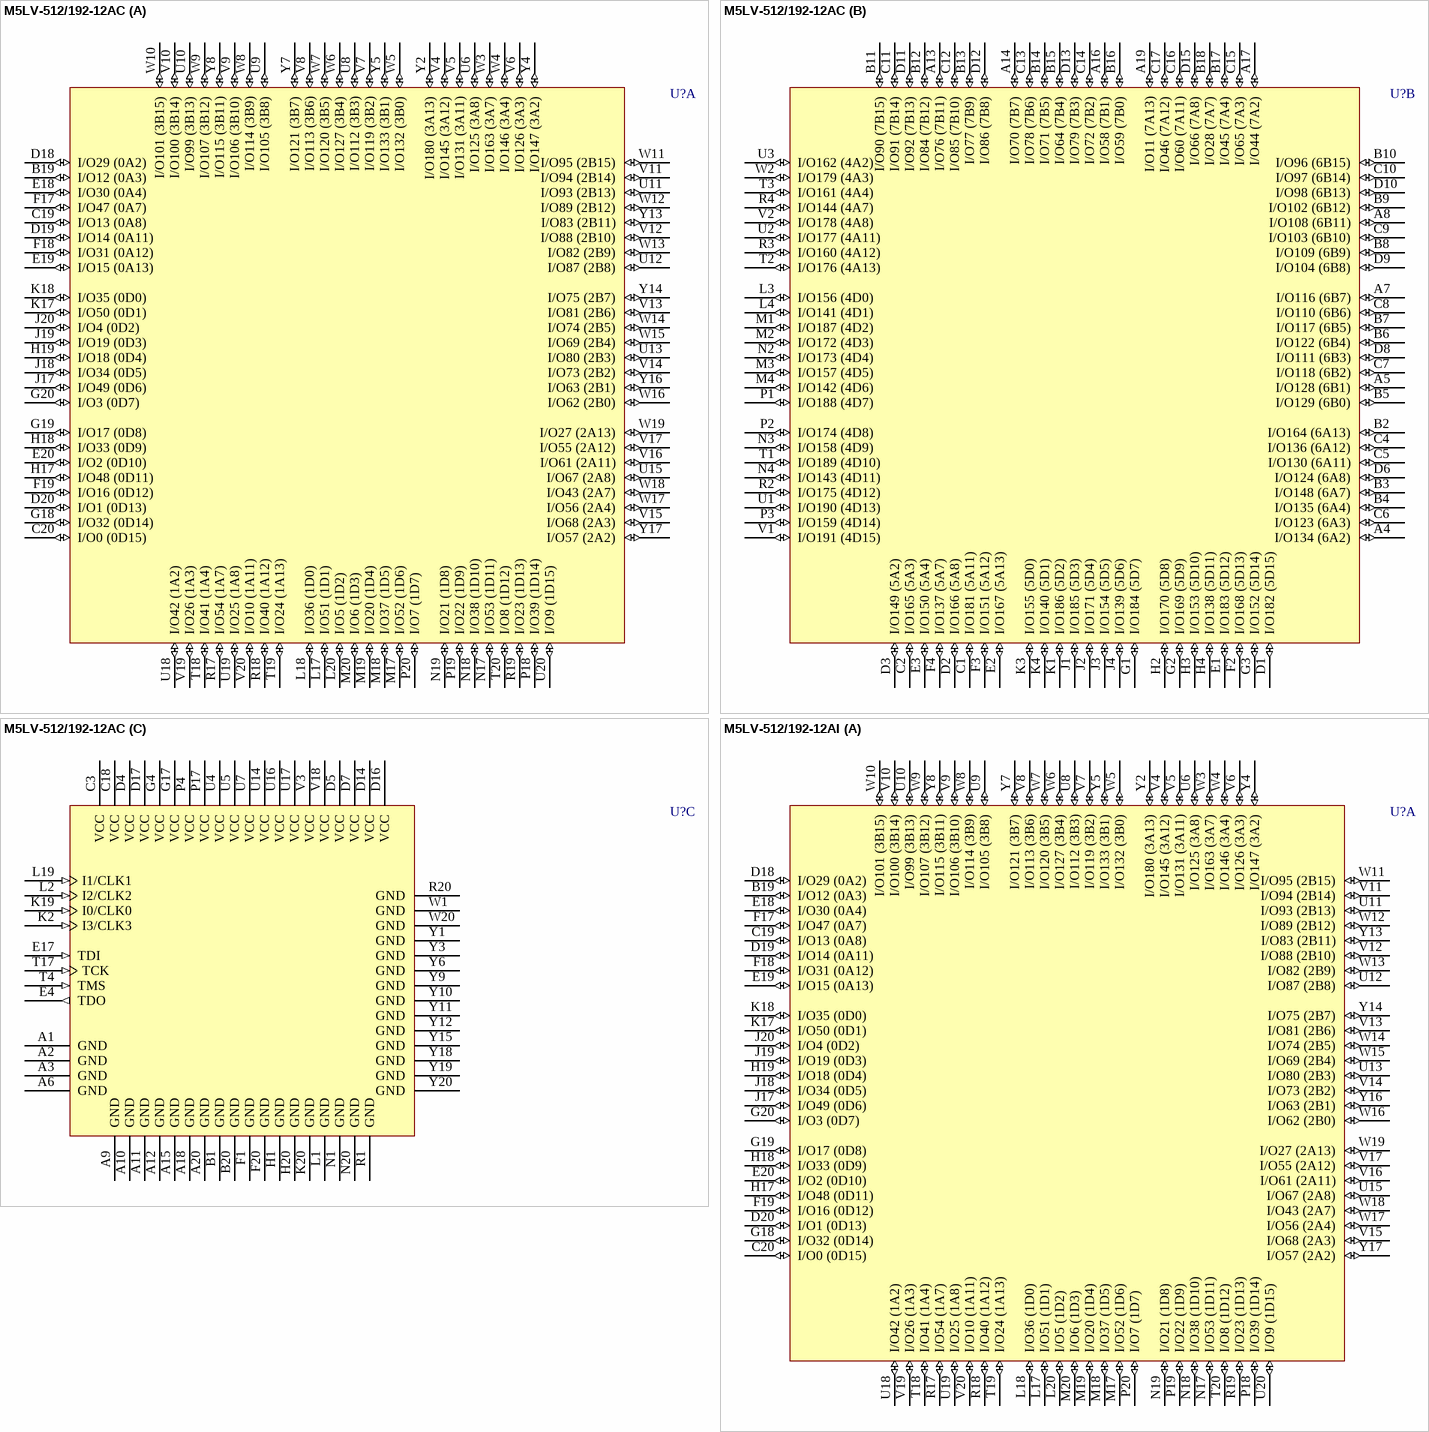
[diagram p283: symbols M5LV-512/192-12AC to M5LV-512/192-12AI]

## M5LV-512/192-12AC
designator U?
High-Density and High-I/O Complex PLD
footprint SBGA256 (BGA, 256-Leads, Body 27x27mm, Pitch 1.27mm)
3D model M5LV-SBGA256 (256-Ball Super Ball Grid Array (SBGA256))
part A pins: B19 I/O12 (0A3) (io), C19 I/O13 (0A8) (io), C20 I/O0 (0D15) (io), D18 I/O29 (0A2) (io), D19 I/O14 (0A11) (io), D20 I/O1 (0D13) (io), E18 I/O30 (0A4) (io), E19 I/O15 (0A13) (io), E20 I/O2 (0D10) (io), F17 I/O47 (0A7) (io), F18 I/O31 (0A12) (io), F19 I/O16 (0D12) (io), G18 I/O32 (0D14) (io), G19 I/O17 (0D8) (io), G20 I/O3 (0D7) (io), H17 I/O48 (0D11) (io), H18 I/O33 (0D9) (io), H19 I/O18 (0D4) (io), J17 I/O49 (0D6) (io), J18 I/O34 (0D5) (io), J19 I/O19 (0D3) (io), J20 I/O4 (0D2) (io), K17 I/O50 (0D1) (io), K18 I/O35 (0D0) (io), L17 I/O51 (1D1) (io), L18 I/O36 (1D0) (io), L20 I/O5 (1D2) (io), M17 I/O52 (1D6) (io), M18 I/O37 (1D5) (io), M19 I/O20 (1D4) (io), M20 I/O6 (1D3) (io), N17 I/O53 (1D11) (io), N18 I/O38 (1D10) (io), N19 I/O21 (1D8) (io), P18 I/O39 (1D14) (io), P19 I/O22 (1D9) (io), P20 I/O7 (1D7) (io), R17 I/O54 (1A7) (io), R18 I/O40 (1A12) (io), R19 I/O23 (1D13) (io), T18 I/O41 (1A4) (io), T19 I/O24 (1A13) (io), T20 I/O8 (1D12) (io), U6 I/O125 (3A8) (io), U8 I/O112 (3B3) (io), U9 I/O105 (3B8) (io), U10 I/O99 (3B13) (io), U11 I/O93 (2B13) (io), U12 I/O87 (2B8) (io), U13 I/O80 (2B3) (io), U15 I/O67 (2A8) (io), U18 I/O42 (1A2) (io), U19 I/O25 (1A8) (io), U20 I/O9 (1D15) (io), V4 I/O145 (3A12) (io), V5 I/O131 (3A11) (io), V6 I/O126 (3A3) (io), V7 I/O119 (3B2) (io), V8 I/O113 (3B6) (io), V9 I/O106 (3B10) (io), V10 I/O100 (3B14) (io), V11 I/O94 (2B14) (io), V12 I/O88 (2B10) (io), V13 I/O81 (2B6) (io), V14 I/O73 (2B2) (io), V15 I/O68 (2A3) (io), V16 I/O61 (2A11) (io), V17 I/O55 (2A12) (io), V19 I/O26 (1A3) (io), V20 I/O10 (1A11) (io), W3 I/O163 (3A7) (io), W4 I/O146 (3A4) (io), W5 I/O132 (3B0) (io), W6 I/O127 (3B4) (io), W7 I/O120 (3B5) (io), W8 I/O114 (3B9) (io), W9 I/O107 (3B12) (io), W10 I/O101 (3B15) (io), W11 I/O95 (2B15) (io), W12 I/O89 (2B12) (io), W13 I/O82 (2B9) (io), W14 I/O74 (2B5) (io), W15 I/O69 (2B4) (io), W16 I/O62 (2B0) (io), W17 I/O56 (2A4) (io), W18 I/O43 (2A7) (io), W19 I/O27 (2A13) (io), Y2 I/O180 (3A13) (io), Y4 I/O147 (3A2) (io), Y5 I/O133 (3B1) (io), Y7 I/O121 (3B7) (io), Y8 I/O115 (3B11) (io), Y13 I/O83 (2B11) (io), Y14 I/O75 (2B7) (io), Y16 I/O63 (2B1) (io), Y17 I/O57 (2A2) (io)
part B pins: A4 I/O134 (6A2) (io), A5 I/O128 (6B1) (io), A7 I/O116 (6B7) (io), A8 I/O108 (6B11) (io), A13 I/O76 (7B11) (io), A14 I/O70 (7B7) (io), A16 I/O58 (7B1) (io), A17 I/O44 (7A2) (io), A19 I/O11 (7A13) (io), B2 I/O164 (6A13) (io), B3 I/O148 (6A7) (io), B4 I/O135 (6A4) (io), B5 I/O129 (6B0) (io), B6 I/O122 (6B4) (io), B7 I/O117 (6B5) (io), B8 I/O109 (6B9) (io), B9 I/O102 (6B12) (io), B10 I/O96 (6B15) (io), B11 I/O90 (7B15) (io), B12 I/O84 (7B12) (io), B13 I/O77 (7B9) (io), B14 I/O71 (7B5) (io), B15 I/O64 (7B4) (io), B16 I/O59 (7B0) (io), B17 I/O45 (7A4) (io), B18 I/O28 (7A7) (io), C1 I/O181 (5A11) (io), C2 I/O165 (5A3) (io), C4 I/O136 (6A12) (io), C5 I/O130 (6A11) (io), C6 I/O123 (6A3) (io), C7 I/O118 (6B2) (io), C8 I/O110 (6B6) (io), C9 I/O103 (6B10) (io), C10 I/O97 (6B14) (io), C11 I/O91 (7B14) (io), C12 I/O85 (7B10) (io), C13 I/O78 (7B6) (io), C14 I/O72 (7B2) (io), C15 I/O65 (7A3) (io), C16 I/O60 (7A11) (io), C17 I/O46 (7A12) (io), D1 I/O182 (5D15) (io), D2 I/O166 (5A8) (io), D3 I/O149 (5A2) (io), D6 I/O124 (6A8) (io), D8 I/O111 (6B3) (io), D9 I/O104 (6B8) (io), D10 I/O98 (6B13) (io), D11 I/O92 (7B13) (io), D12 I/O86 (7B8) (io), D13 I/O79 (7B3) (io), D15 I/O66 (7A8) (io), E1 I/O183 (5D12) (io), E2 I/O167 (5A13) (io), E3 I/O150 (5A4) (io), F2 I/O168 (5D13) (io), F3 I/O151 (5A12) (io), F4 I/O137 (5A7) (io), G1 I/O184 (5D7) (io), G2 I/O169 (5D9) (io), G3 I/O152 (5D14) (io), H2 I/O170 (5D8) (io), H3 I/O153 (5D10) (io), H4 I/O138 (5D11) (io), J1 I/O185 (5D3) (io), J2 I/O171 (5D4) (io), J3 I/O154 (5D5) (io), J4 I/O139 (5D6) (io), K1 I/O186 (5D2) (io), K3 I/O155 (5D0) (io), K4 I/O140 (5D1) (io), L3 I/O156 (4D0) (io), L4 I/O141 (4D1) (io), M1 I/O187 (4D2) (io), M2 I/O172 (4D3) (io), M3 I/O157 (4D5) (io), M4 I/O142 (4D6) (io), N2 I/O173 (4D4) (io), N3 I/O158 (4D9) (io), N4 I/O143 (4D11) (io), P1 I/O188 (4D7) (io), P2 I/O174 (4D8) (io), P3 I/O159 (4D14) (io), R2 I/O175 (4D12) (io), R3 I/O160 (4A12) (io), R4 I/O144 (4A7) (io), T1 I/O189 (4D10) (io), T2 I/O176 (4A13) (io), T3 I/O161 (4A4) (io), U1 I/O190 (4D13) (io), U2 I/O177 (4A11) (io), U3 I/O162 (4A2) (io), V1 I/O191 (4D15) (io), V2 I/O178 (4A8) (io), W2 I/O179 (4A3) (io)
part C pins: A1 GND (power), A2 GND (power), A3 GND (power), A6 GND (power), A9 GND (power), A10 GND (power), A11 GND (power), A12 GND (power), A15 GND (power), A18 GND (power), A20 GND (power), B1 GND (power), B20 GND (power), C3 VCC (power), C18 VCC (power), D4 VCC (power), D5 VCC (power), D7 VCC (power), D14 VCC (power), D16 VCC (power), D17 VCC (power), E4 TDO (out), E17 TDI (in), F1 GND (power), F20 GND (power), G4 VCC (power), G17 VCC (power), H1 GND (power), H20 GND (power), K2 I3/CLK3 (in), K19 I0/CLK0 (in), K20 GND (power), L1 GND (power), L2 I2/CLK2 (in), L19 I1/CLK1 (in), N1 GND (power), N20 GND (power), P4 VCC (power), P17 VCC (power), R1 GND (power), R20 GND (power), T4 TMS (in), T17 TCK (in), U4 VCC (power), U5 VCC (power), U7 VCC (power), U14 VCC (power), U16 VCC (power), U17 VCC (power), V3 VCC (power), V18 VCC (power), W1 GND (power), W20 GND (power), Y1 GND (power), Y3 GND (power), Y6 GND (power), Y9 GND (power), Y10 GND (power), Y11 GND (power), Y12 GND (power), Y15 GND (power), Y18 GND (power), Y19 GND (power), Y20 GND (power)

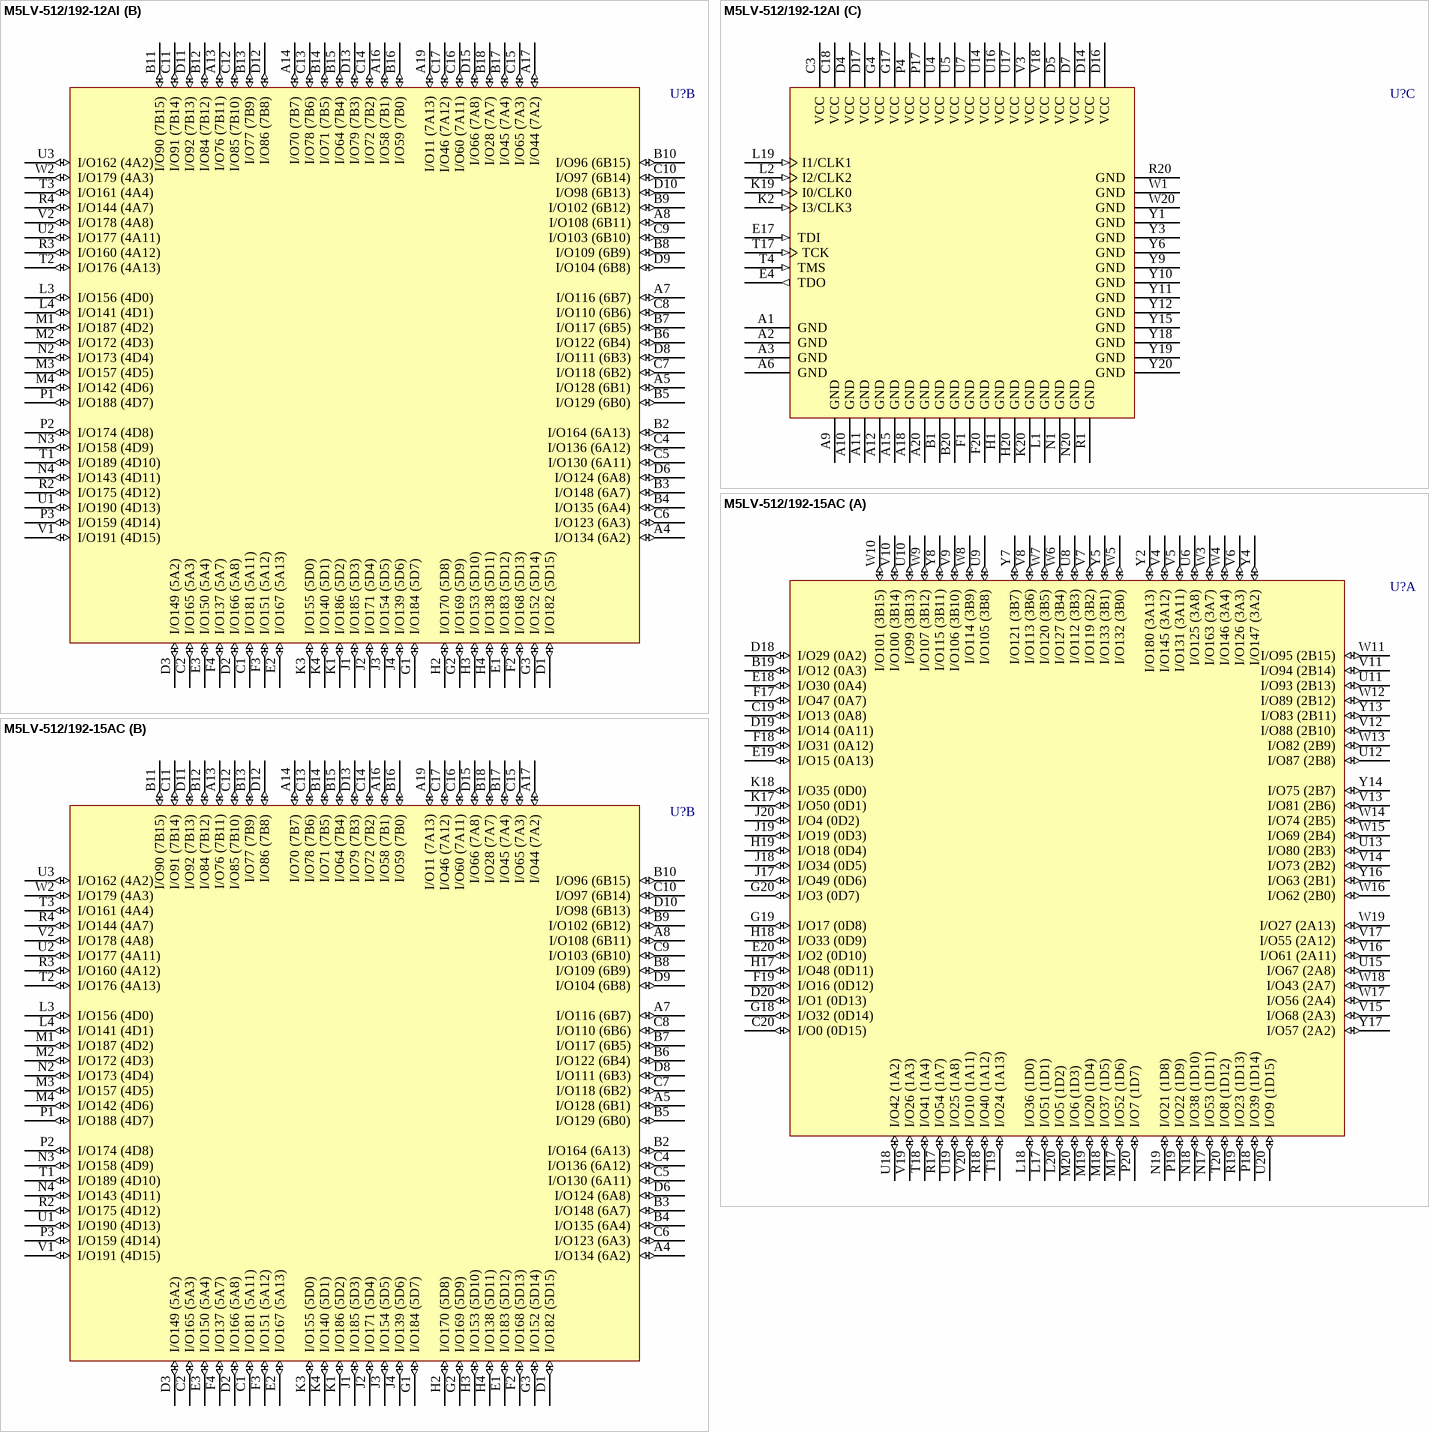
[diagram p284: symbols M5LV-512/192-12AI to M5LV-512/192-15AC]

## M5LV-512/192-12AI
designator U?
High-Density and High-I/O Complex PLD
footprint SBGA256 (BGA, 256-Leads, Body 27x27mm, Pitch 1.27mm)
3D model M5LV-SBGA256 (256-Ball Super Ball Grid Array (SBGA256))
part A pins: B19 I/O12 (0A3) (io), C19 I/O13 (0A8) (io), C20 I/O0 (0D15) (io), D18 I/O29 (0A2) (io), D19 I/O14 (0A11) (io), D20 I/O1 (0D13) (io), E18 I/O30 (0A4) (io), E19 I/O15 (0A13) (io), E20 I/O2 (0D10) (io), F17 I/O47 (0A7) (io), F18 I/O31 (0A12) (io), F19 I/O16 (0D12) (io), G18 I/O32 (0D14) (io), G19 I/O17 (0D8) (io), G20 I/O3 (0D7) (io), H17 I/O48 (0D11) (io), H18 I/O33 (0D9) (io), H19 I/O18 (0D4) (io), J17 I/O49 (0D6) (io), J18 I/O34 (0D5) (io), J19 I/O19 (0D3) (io), J20 I/O4 (0D2) (io), K17 I/O50 (0D1) (io), K18 I/O35 (0D0) (io), L17 I/O51 (1D1) (io), L18 I/O36 (1D0) (io), L20 I/O5 (1D2) (io), M17 I/O52 (1D6) (io), M18 I/O37 (1D5) (io), M19 I/O20 (1D4) (io), M20 I/O6 (1D3) (io), N17 I/O53 (1D11) (io), N18 I/O38 (1D10) (io), N19 I/O21 (1D8) (io), P18 I/O39 (1D14) (io), P19 I/O22 (1D9) (io), P20 I/O7 (1D7) (io), R17 I/O54 (1A7) (io), R18 I/O40 (1A12) (io), R19 I/O23 (1D13) (io), T18 I/O41 (1A4) (io), T19 I/O24 (1A13) (io), T20 I/O8 (1D12) (io), U6 I/O125 (3A8) (io), U8 I/O112 (3B3) (io), U9 I/O105 (3B8) (io), U10 I/O99 (3B13) (io), U11 I/O93 (2B13) (io), U12 I/O87 (2B8) (io), U13 I/O80 (2B3) (io), U15 I/O67 (2A8) (io), U18 I/O42 (1A2) (io), U19 I/O25 (1A8) (io), U20 I/O9 (1D15) (io), V4 I/O145 (3A12) (io), V5 I/O131 (3A11) (io), V6 I/O126 (3A3) (io), V7 I/O119 (3B2) (io), V8 I/O113 (3B6) (io), V9 I/O106 (3B10) (io), V10 I/O100 (3B14) (io), V11 I/O94 (2B14) (io), V12 I/O88 (2B10) (io), V13 I/O81 (2B6) (io), V14 I/O73 (2B2) (io), V15 I/O68 (2A3) (io), V16 I/O61 (2A11) (io), V17 I/O55 (2A12) (io), V19 I/O26 (1A3) (io), V20 I/O10 (1A11) (io), W3 I/O163 (3A7) (io), W4 I/O146 (3A4) (io), W5 I/O132 (3B0) (io), W6 I/O127 (3B4) (io), W7 I/O120 (3B5) (io), W8 I/O114 (3B9) (io), W9 I/O107 (3B12) (io), W10 I/O101 (3B15) (io), W11 I/O95 (2B15) (io), W12 I/O89 (2B12) (io), W13 I/O82 (2B9) (io), W14 I/O74 (2B5) (io), W15 I/O69 (2B4) (io), W16 I/O62 (2B0) (io), W17 I/O56 (2A4) (io), W18 I/O43 (2A7) (io), W19 I/O27 (2A13) (io), Y2 I/O180 (3A13) (io), Y4 I/O147 (3A2) (io), Y5 I/O133 (3B1) (io), Y7 I/O121 (3B7) (io), Y8 I/O115 (3B11) (io), Y13 I/O83 (2B11) (io), Y14 I/O75 (2B7) (io), Y16 I/O63 (2B1) (io), Y17 I/O57 (2A2) (io)
part B pins: A4 I/O134 (6A2) (io), A5 I/O128 (6B1) (io), A7 I/O116 (6B7) (io), A8 I/O108 (6B11) (io), A13 I/O76 (7B11) (io), A14 I/O70 (7B7) (io), A16 I/O58 (7B1) (io), A17 I/O44 (7A2) (io), A19 I/O11 (7A13) (io), B2 I/O164 (6A13) (io), B3 I/O148 (6A7) (io), B4 I/O135 (6A4) (io), B5 I/O129 (6B0) (io), B6 I/O122 (6B4) (io), B7 I/O117 (6B5) (io), B8 I/O109 (6B9) (io), B9 I/O102 (6B12) (io), B10 I/O96 (6B15) (io), B11 I/O90 (7B15) (io), B12 I/O84 (7B12) (io), B13 I/O77 (7B9) (io), B14 I/O71 (7B5) (io), B15 I/O64 (7B4) (io), B16 I/O59 (7B0) (io), B17 I/O45 (7A4) (io), B18 I/O28 (7A7) (io), C1 I/O181 (5A11) (io), C2 I/O165 (5A3) (io), C4 I/O136 (6A12) (io), C5 I/O130 (6A11) (io), C6 I/O123 (6A3) (io), C7 I/O118 (6B2) (io), C8 I/O110 (6B6) (io), C9 I/O103 (6B10) (io), C10 I/O97 (6B14) (io), C11 I/O91 (7B14) (io), C12 I/O85 (7B10) (io), C13 I/O78 (7B6) (io), C14 I/O72 (7B2) (io), C15 I/O65 (7A3) (io), C16 I/O60 (7A11) (io), C17 I/O46 (7A12) (io), D1 I/O182 (5D15) (io), D2 I/O166 (5A8) (io), D3 I/O149 (5A2) (io), D6 I/O124 (6A8) (io), D8 I/O111 (6B3) (io), D9 I/O104 (6B8) (io), D10 I/O98 (6B13) (io), D11 I/O92 (7B13) (io), D12 I/O86 (7B8) (io), D13 I/O79 (7B3) (io), D15 I/O66 (7A8) (io), E1 I/O183 (5D12) (io), E2 I/O167 (5A13) (io), E3 I/O150 (5A4) (io), F2 I/O168 (5D13) (io), F3 I/O151 (5A12) (io), F4 I/O137 (5A7) (io), G1 I/O184 (5D7) (io), G2 I/O169 (5D9) (io), G3 I/O152 (5D14) (io), H2 I/O170 (5D8) (io), H3 I/O153 (5D10) (io), H4 I/O138 (5D11) (io), J1 I/O185 (5D3) (io), J2 I/O171 (5D4) (io), J3 I/O154 (5D5) (io), J4 I/O139 (5D6) (io), K1 I/O186 (5D2) (io), K3 I/O155 (5D0) (io), K4 I/O140 (5D1) (io), L3 I/O156 (4D0) (io), L4 I/O141 (4D1) (io), M1 I/O187 (4D2) (io), M2 I/O172 (4D3) (io), M3 I/O157 (4D5) (io), M4 I/O142 (4D6) (io), N2 I/O173 (4D4) (io), N3 I/O158 (4D9) (io), N4 I/O143 (4D11) (io), P1 I/O188 (4D7) (io), P2 I/O174 (4D8) (io), P3 I/O159 (4D14) (io), R2 I/O175 (4D12) (io), R3 I/O160 (4A12) (io), R4 I/O144 (4A7) (io), T1 I/O189 (4D10) (io), T2 I/O176 (4A13) (io), T3 I/O161 (4A4) (io), U1 I/O190 (4D13) (io), U2 I/O177 (4A11) (io), U3 I/O162 (4A2) (io), V1 I/O191 (4D15) (io), V2 I/O178 (4A8) (io), W2 I/O179 (4A3) (io)
part C pins: A1 GND (power), A2 GND (power), A3 GND (power), A6 GND (power), A9 GND (power), A10 GND (power), A11 GND (power), A12 GND (power), A15 GND (power), A18 GND (power), A20 GND (power), B1 GND (power), B20 GND (power), C3 VCC (power), C18 VCC (power), D4 VCC (power), D5 VCC (power), D7 VCC (power), D14 VCC (power), D16 VCC (power), D17 VCC (power), E4 TDO (out), E17 TDI (in), F1 GND (power), F20 GND (power), G4 VCC (power), G17 VCC (power), H1 GND (power), H20 GND (power), K2 I3/CLK3 (in), K19 I0/CLK0 (in), K20 GND (power), L1 GND (power), L2 I2/CLK2 (in), L19 I1/CLK1 (in), N1 GND (power), N20 GND (power), P4 VCC (power), P17 VCC (power), R1 GND (power), R20 GND (power), T4 TMS (in), T17 TCK (in), U4 VCC (power), U5 VCC (power), U7 VCC (power), U14 VCC (power), U16 VCC (power), U17 VCC (power), V3 VCC (power), V18 VCC (power), W1 GND (power), W20 GND (power), Y1 GND (power), Y3 GND (power), Y6 GND (power), Y9 GND (power), Y10 GND (power), Y11 GND (power), Y12 GND (power), Y15 GND (power), Y18 GND (power), Y19 GND (power), Y20 GND (power)

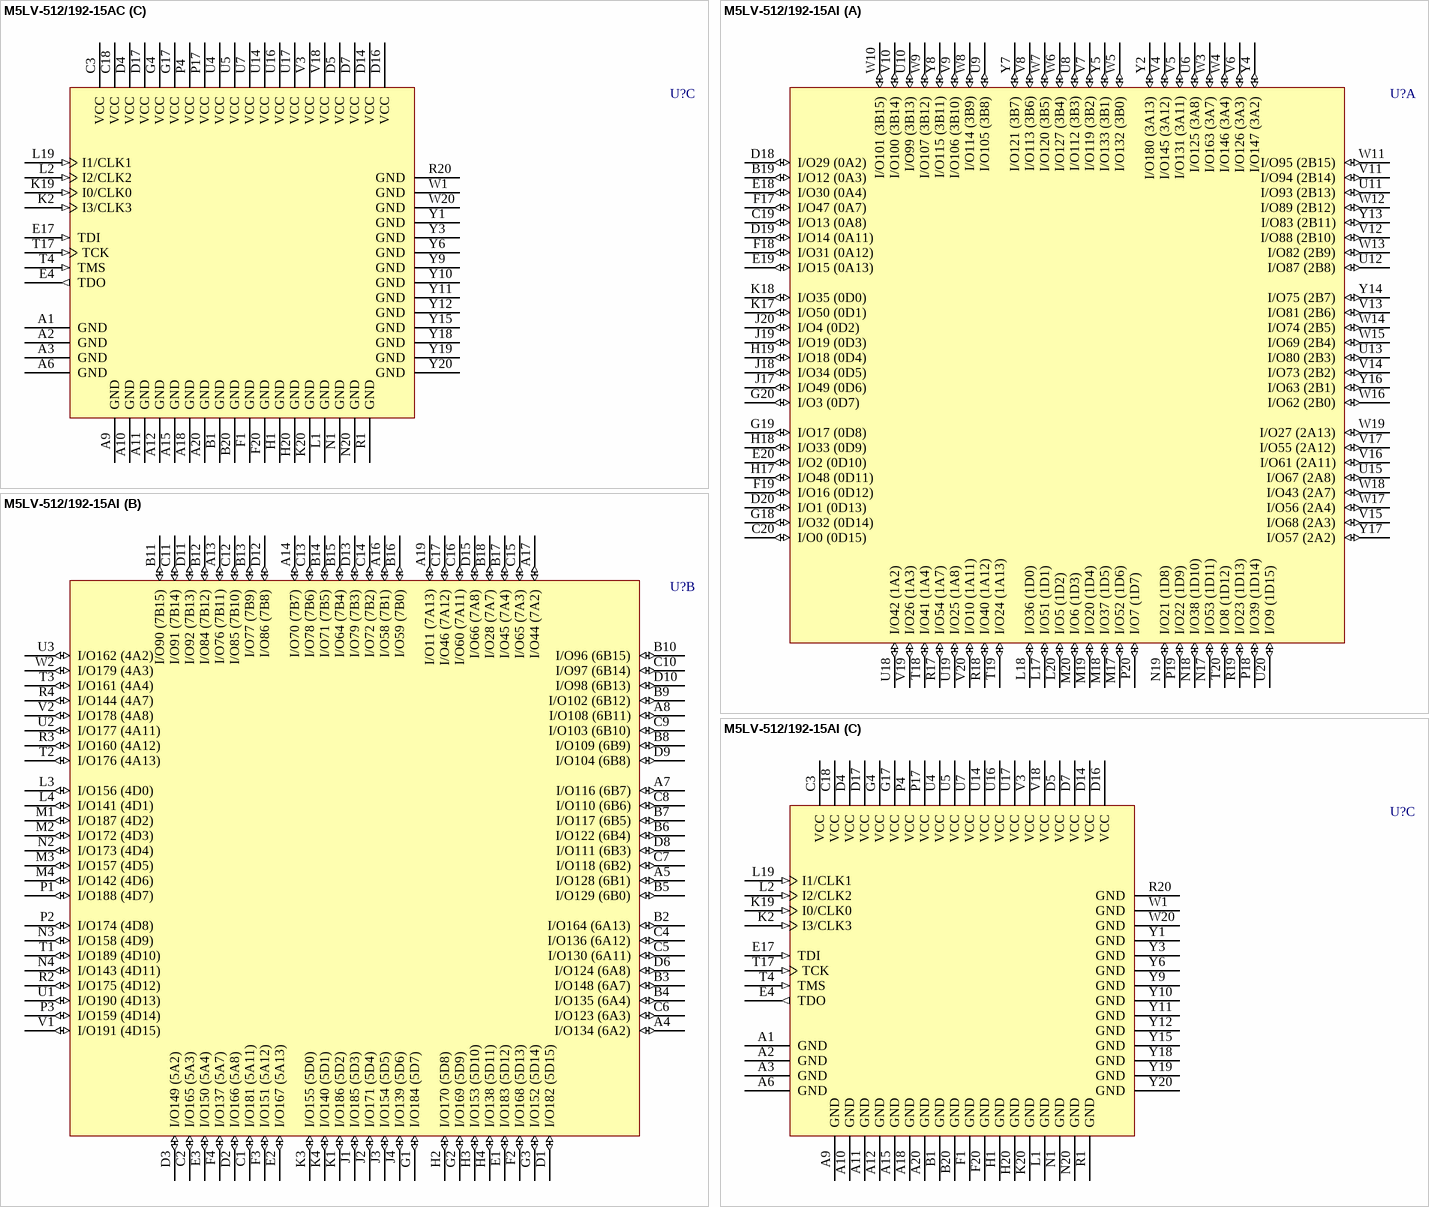
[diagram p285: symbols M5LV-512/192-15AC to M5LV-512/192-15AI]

## M5LV-512/192-15AC
designator U?
High-Density and High-I/O Complex PLD
footprint SBGA256 (BGA, 256-Leads, Body 27x27mm, Pitch 1.27mm)
3D model M5LV-SBGA256 (256-Ball Super Ball Grid Array (SBGA256))
part A pins: B19 I/O12 (0A3) (io), C19 I/O13 (0A8) (io), C20 I/O0 (0D15) (io), D18 I/O29 (0A2) (io), D19 I/O14 (0A11) (io), D20 I/O1 (0D13) (io), E18 I/O30 (0A4) (io), E19 I/O15 (0A13) (io), E20 I/O2 (0D10) (io), F17 I/O47 (0A7) (io), F18 I/O31 (0A12) (io), F19 I/O16 (0D12) (io), G18 I/O32 (0D14) (io), G19 I/O17 (0D8) (io), G20 I/O3 (0D7) (io), H17 I/O48 (0D11) (io), H18 I/O33 (0D9) (io), H19 I/O18 (0D4) (io), J17 I/O49 (0D6) (io), J18 I/O34 (0D5) (io), J19 I/O19 (0D3) (io), J20 I/O4 (0D2) (io), K17 I/O50 (0D1) (io), K18 I/O35 (0D0) (io), L17 I/O51 (1D1) (io), L18 I/O36 (1D0) (io), L20 I/O5 (1D2) (io), M17 I/O52 (1D6) (io), M18 I/O37 (1D5) (io), M19 I/O20 (1D4) (io), M20 I/O6 (1D3) (io), N17 I/O53 (1D11) (io), N18 I/O38 (1D10) (io), N19 I/O21 (1D8) (io), P18 I/O39 (1D14) (io), P19 I/O22 (1D9) (io), P20 I/O7 (1D7) (io), R17 I/O54 (1A7) (io), R18 I/O40 (1A12) (io), R19 I/O23 (1D13) (io), T18 I/O41 (1A4) (io), T19 I/O24 (1A13) (io), T20 I/O8 (1D12) (io), U6 I/O125 (3A8) (io), U8 I/O112 (3B3) (io), U9 I/O105 (3B8) (io), U10 I/O99 (3B13) (io), U11 I/O93 (2B13) (io), U12 I/O87 (2B8) (io), U13 I/O80 (2B3) (io), U15 I/O67 (2A8) (io), U18 I/O42 (1A2) (io), U19 I/O25 (1A8) (io), U20 I/O9 (1D15) (io), V4 I/O145 (3A12) (io), V5 I/O131 (3A11) (io), V6 I/O126 (3A3) (io), V7 I/O119 (3B2) (io), V8 I/O113 (3B6) (io), V9 I/O106 (3B10) (io), V10 I/O100 (3B14) (io), V11 I/O94 (2B14) (io), V12 I/O88 (2B10) (io), V13 I/O81 (2B6) (io), V14 I/O73 (2B2) (io), V15 I/O68 (2A3) (io), V16 I/O61 (2A11) (io), V17 I/O55 (2A12) (io), V19 I/O26 (1A3) (io), V20 I/O10 (1A11) (io), W3 I/O163 (3A7) (io), W4 I/O146 (3A4) (io), W5 I/O132 (3B0) (io), W6 I/O127 (3B4) (io), W7 I/O120 (3B5) (io), W8 I/O114 (3B9) (io), W9 I/O107 (3B12) (io), W10 I/O101 (3B15) (io), W11 I/O95 (2B15) (io), W12 I/O89 (2B12) (io), W13 I/O82 (2B9) (io), W14 I/O74 (2B5) (io), W15 I/O69 (2B4) (io), W16 I/O62 (2B0) (io), W17 I/O56 (2A4) (io), W18 I/O43 (2A7) (io), W19 I/O27 (2A13) (io), Y2 I/O180 (3A13) (io), Y4 I/O147 (3A2) (io), Y5 I/O133 (3B1) (io), Y7 I/O121 (3B7) (io), Y8 I/O115 (3B11) (io), Y13 I/O83 (2B11) (io), Y14 I/O75 (2B7) (io), Y16 I/O63 (2B1) (io), Y17 I/O57 (2A2) (io)
part B pins: A4 I/O134 (6A2) (io), A5 I/O128 (6B1) (io), A7 I/O116 (6B7) (io), A8 I/O108 (6B11) (io), A13 I/O76 (7B11) (io), A14 I/O70 (7B7) (io), A16 I/O58 (7B1) (io), A17 I/O44 (7A2) (io), A19 I/O11 (7A13) (io), B2 I/O164 (6A13) (io), B3 I/O148 (6A7) (io), B4 I/O135 (6A4) (io), B5 I/O129 (6B0) (io), B6 I/O122 (6B4) (io), B7 I/O117 (6B5) (io), B8 I/O109 (6B9) (io), B9 I/O102 (6B12) (io), B10 I/O96 (6B15) (io), B11 I/O90 (7B15) (io), B12 I/O84 (7B12) (io), B13 I/O77 (7B9) (io), B14 I/O71 (7B5) (io), B15 I/O64 (7B4) (io), B16 I/O59 (7B0) (io), B17 I/O45 (7A4) (io), B18 I/O28 (7A7) (io), C1 I/O181 (5A11) (io), C2 I/O165 (5A3) (io), C4 I/O136 (6A12) (io), C5 I/O130 (6A11) (io), C6 I/O123 (6A3) (io), C7 I/O118 (6B2) (io), C8 I/O110 (6B6) (io), C9 I/O103 (6B10) (io), C10 I/O97 (6B14) (io), C11 I/O91 (7B14) (io), C12 I/O85 (7B10) (io), C13 I/O78 (7B6) (io), C14 I/O72 (7B2) (io), C15 I/O65 (7A3) (io), C16 I/O60 (7A11) (io), C17 I/O46 (7A12) (io), D1 I/O182 (5D15) (io), D2 I/O166 (5A8) (io), D3 I/O149 (5A2) (io), D6 I/O124 (6A8) (io), D8 I/O111 (6B3) (io), D9 I/O104 (6B8) (io), D10 I/O98 (6B13) (io), D11 I/O92 (7B13) (io), D12 I/O86 (7B8) (io), D13 I/O79 (7B3) (io), D15 I/O66 (7A8) (io), E1 I/O183 (5D12) (io), E2 I/O167 (5A13) (io), E3 I/O150 (5A4) (io), F2 I/O168 (5D13) (io), F3 I/O151 (5A12) (io), F4 I/O137 (5A7) (io), G1 I/O184 (5D7) (io), G2 I/O169 (5D9) (io), G3 I/O152 (5D14) (io), H2 I/O170 (5D8) (io), H3 I/O153 (5D10) (io), H4 I/O138 (5D11) (io), J1 I/O185 (5D3) (io), J2 I/O171 (5D4) (io), J3 I/O154 (5D5) (io), J4 I/O139 (5D6) (io), K1 I/O186 (5D2) (io), K3 I/O155 (5D0) (io), K4 I/O140 (5D1) (io), L3 I/O156 (4D0) (io), L4 I/O141 (4D1) (io), M1 I/O187 (4D2) (io), M2 I/O172 (4D3) (io), M3 I/O157 (4D5) (io), M4 I/O142 (4D6) (io), N2 I/O173 (4D4) (io), N3 I/O158 (4D9) (io), N4 I/O143 (4D11) (io), P1 I/O188 (4D7) (io), P2 I/O174 (4D8) (io), P3 I/O159 (4D14) (io), R2 I/O175 (4D12) (io), R3 I/O160 (4A12) (io), R4 I/O144 (4A7) (io), T1 I/O189 (4D10) (io), T2 I/O176 (4A13) (io), T3 I/O161 (4A4) (io), U1 I/O190 (4D13) (io), U2 I/O177 (4A11) (io), U3 I/O162 (4A2) (io), V1 I/O191 (4D15) (io), V2 I/O178 (4A8) (io), W2 I/O179 (4A3) (io)
part C pins: A1 GND (power), A2 GND (power), A3 GND (power), A6 GND (power), A9 GND (power), A10 GND (power), A11 GND (power), A12 GND (power), A15 GND (power), A18 GND (power), A20 GND (power), B1 GND (power), B20 GND (power), C3 VCC (power), C18 VCC (power), D4 VCC (power), D5 VCC (power), D7 VCC (power), D14 VCC (power), D16 VCC (power), D17 VCC (power), E4 TDO (out), E17 TDI (in), F1 GND (power), F20 GND (power), G4 VCC (power), G17 VCC (power), H1 GND (power), H20 GND (power), K2 I3/CLK3 (in), K19 I0/CLK0 (in), K20 GND (power), L1 GND (power), L2 I2/CLK2 (in), L19 I1/CLK1 (in), N1 GND (power), N20 GND (power), P4 VCC (power), P17 VCC (power), R1 GND (power), R20 GND (power), T4 TMS (in), T17 TCK (in), U4 VCC (power), U5 VCC (power), U7 VCC (power), U14 VCC (power), U16 VCC (power), U17 VCC (power), V3 VCC (power), V18 VCC (power), W1 GND (power), W20 GND (power), Y1 GND (power), Y3 GND (power), Y6 GND (power), Y9 GND (power), Y10 GND (power), Y11 GND (power), Y12 GND (power), Y15 GND (power), Y18 GND (power), Y19 GND (power), Y20 GND (power)

## M5LV-512/192-15AI
designator U?
High-Density and High-I/O Complex PLD
footprint SBGA256 (BGA, 256-Leads, Body 27x27mm, Pitch 1.27mm)
3D model M5LV-SBGA256 (256-Ball Super Ball Grid Array (SBGA256))
part A pins: B19 I/O12 (0A3) (io), C19 I/O13 (0A8) (io), C20 I/O0 (0D15) (io), D18 I/O29 (0A2) (io), D19 I/O14 (0A11) (io), D20 I/O1 (0D13) (io), E18 I/O30 (0A4) (io), E19 I/O15 (0A13) (io), E20 I/O2 (0D10) (io), F17 I/O47 (0A7) (io), F18 I/O31 (0A12) (io), F19 I/O16 (0D12) (io), G18 I/O32 (0D14) (io), G19 I/O17 (0D8) (io), G20 I/O3 (0D7) (io), H17 I/O48 (0D11) (io), H18 I/O33 (0D9) (io), H19 I/O18 (0D4) (io), J17 I/O49 (0D6) (io), J18 I/O34 (0D5) (io), J19 I/O19 (0D3) (io), J20 I/O4 (0D2) (io), K17 I/O50 (0D1) (io), K18 I/O35 (0D0) (io), L17 I/O51 (1D1) (io), L18 I/O36 (1D0) (io), L20 I/O5 (1D2) (io), M17 I/O52 (1D6) (io), M18 I/O37 (1D5) (io), M19 I/O20 (1D4) (io), M20 I/O6 (1D3) (io), N17 I/O53 (1D11) (io), N18 I/O38 (1D10) (io), N19 I/O21 (1D8) (io), P18 I/O39 (1D14) (io), P19 I/O22 (1D9) (io), P20 I/O7 (1D7) (io), R17 I/O54 (1A7) (io), R18 I/O40 (1A12) (io), R19 I/O23 (1D13) (io), T18 I/O41 (1A4) (io), T19 I/O24 (1A13) (io), T20 I/O8 (1D12) (io), U6 I/O125 (3A8) (io), U8 I/O112 (3B3) (io), U9 I/O105 (3B8) (io), U10 I/O99 (3B13) (io), U11 I/O93 (2B13) (io), U12 I/O87 (2B8) (io), U13 I/O80 (2B3) (io), U15 I/O67 (2A8) (io), U18 I/O42 (1A2) (io), U19 I/O25 (1A8) (io), U20 I/O9 (1D15) (io), V4 I/O145 (3A12) (io), V5 I/O131 (3A11) (io), V6 I/O126 (3A3) (io), V7 I/O119 (3B2) (io), V8 I/O113 (3B6) (io), V9 I/O106 (3B10) (io), V10 I/O100 (3B14) (io), V11 I/O94 (2B14) (io), V12 I/O88 (2B10) (io), V13 I/O81 (2B6) (io), V14 I/O73 (2B2) (io), V15 I/O68 (2A3) (io), V16 I/O61 (2A11) (io), V17 I/O55 (2A12) (io), V19 I/O26 (1A3) (io), V20 I/O10 (1A11) (io), W3 I/O163 (3A7) (io), W4 I/O146 (3A4) (io), W5 I/O132 (3B0) (io), W6 I/O127 (3B4) (io), W7 I/O120 (3B5) (io), W8 I/O114 (3B9) (io), W9 I/O107 (3B12) (io), W10 I/O101 (3B15) (io), W11 I/O95 (2B15) (io), W12 I/O89 (2B12) (io), W13 I/O82 (2B9) (io), W14 I/O74 (2B5) (io), W15 I/O69 (2B4) (io), W16 I/O62 (2B0) (io), W17 I/O56 (2A4) (io), W18 I/O43 (2A7) (io), W19 I/O27 (2A13) (io), Y2 I/O180 (3A13) (io), Y4 I/O147 (3A2) (io), Y5 I/O133 (3B1) (io), Y7 I/O121 (3B7) (io), Y8 I/O115 (3B11) (io), Y13 I/O83 (2B11) (io), Y14 I/O75 (2B7) (io), Y16 I/O63 (2B1) (io), Y17 I/O57 (2A2) (io)
part B pins: A4 I/O134 (6A2) (io), A5 I/O128 (6B1) (io), A7 I/O116 (6B7) (io), A8 I/O108 (6B11) (io), A13 I/O76 (7B11) (io), A14 I/O70 (7B7) (io), A16 I/O58 (7B1) (io), A17 I/O44 (7A2) (io), A19 I/O11 (7A13) (io), B2 I/O164 (6A13) (io), B3 I/O148 (6A7) (io), B4 I/O135 (6A4) (io), B5 I/O129 (6B0) (io), B6 I/O122 (6B4) (io), B7 I/O117 (6B5) (io), B8 I/O109 (6B9) (io), B9 I/O102 (6B12) (io), B10 I/O96 (6B15) (io), B11 I/O90 (7B15) (io), B12 I/O84 (7B12) (io), B13 I/O77 (7B9) (io), B14 I/O71 (7B5) (io), B15 I/O64 (7B4) (io), B16 I/O59 (7B0) (io), B17 I/O45 (7A4) (io), B18 I/O28 (7A7) (io), C1 I/O181 (5A11) (io), C2 I/O165 (5A3) (io), C4 I/O136 (6A12) (io), C5 I/O130 (6A11) (io), C6 I/O123 (6A3) (io), C7 I/O118 (6B2) (io), C8 I/O110 (6B6) (io), C9 I/O103 (6B10) (io), C10 I/O97 (6B14) (io), C11 I/O91 (7B14) (io), C12 I/O85 (7B10) (io), C13 I/O78 (7B6) (io), C14 I/O72 (7B2) (io), C15 I/O65 (7A3) (io), C16 I/O60 (7A11) (io), C17 I/O46 (7A12) (io), D1 I/O182 (5D15) (io), D2 I/O166 (5A8) (io), D3 I/O149 (5A2) (io), D6 I/O124 (6A8) (io), D8 I/O111 (6B3) (io), D9 I/O104 (6B8) (io), D10 I/O98 (6B13) (io), D11 I/O92 (7B13) (io), D12 I/O86 (7B8) (io), D13 I/O79 (7B3) (io), D15 I/O66 (7A8) (io), E1 I/O183 (5D12) (io), E2 I/O167 (5A13) (io), E3 I/O150 (5A4) (io), F2 I/O168 (5D13) (io), F3 I/O151 (5A12) (io), F4 I/O137 (5A7) (io), G1 I/O184 (5D7) (io), G2 I/O169 (5D9) (io), G3 I/O152 (5D14) (io), H2 I/O170 (5D8) (io), H3 I/O153 (5D10) (io), H4 I/O138 (5D11) (io), J1 I/O185 (5D3) (io), J2 I/O171 (5D4) (io), J3 I/O154 (5D5) (io), J4 I/O139 (5D6) (io), K1 I/O186 (5D2) (io), K3 I/O155 (5D0) (io), K4 I/O140 (5D1) (io), L3 I/O156 (4D0) (io), L4 I/O141 (4D1) (io), M1 I/O187 (4D2) (io), M2 I/O172 (4D3) (io), M3 I/O157 (4D5) (io), M4 I/O142 (4D6) (io), N2 I/O173 (4D4) (io), N3 I/O158 (4D9) (io), N4 I/O143 (4D11) (io), P1 I/O188 (4D7) (io), P2 I/O174 (4D8) (io), P3 I/O159 (4D14) (io), R2 I/O175 (4D12) (io), R3 I/O160 (4A12) (io), R4 I/O144 (4A7) (io), T1 I/O189 (4D10) (io), T2 I/O176 (4A13) (io), T3 I/O161 (4A4) (io), U1 I/O190 (4D13) (io), U2 I/O177 (4A11) (io), U3 I/O162 (4A2) (io), V1 I/O191 (4D15) (io), V2 I/O178 (4A8) (io), W2 I/O179 (4A3) (io)
part C pins: A1 GND (power), A2 GND (power), A3 GND (power), A6 GND (power), A9 GND (power), A10 GND (power), A11 GND (power), A12 GND (power), A15 GND (power), A18 GND (power), A20 GND (power), B1 GND (power), B20 GND (power), C3 VCC (power), C18 VCC (power), D4 VCC (power), D5 VCC (power), D7 VCC (power), D14 VCC (power), D16 VCC (power), D17 VCC (power), E4 TDO (out), E17 TDI (in), F1 GND (power), F20 GND (power), G4 VCC (power), G17 VCC (power), H1 GND (power), H20 GND (power), K2 I3/CLK3 (in), K19 I0/CLK0 (in), K20 GND (power), L1 GND (power), L2 I2/CLK2 (in), L19 I1/CLK1 (in), N1 GND (power), N20 GND (power), P4 VCC (power), P17 VCC (power), R1 GND (power), R20 GND (power), T4 TMS (in), T17 TCK (in), U4 VCC (power), U5 VCC (power), U7 VCC (power), U14 VCC (power), U16 VCC (power), U17 VCC (power), V3 VCC (power), V18 VCC (power), W1 GND (power), W20 GND (power), Y1 GND (power), Y3 GND (power), Y6 GND (power), Y9 GND (power), Y10 GND (power), Y11 GND (power), Y12 GND (power), Y15 GND (power), Y18 GND (power), Y19 GND (power), Y20 GND (power)

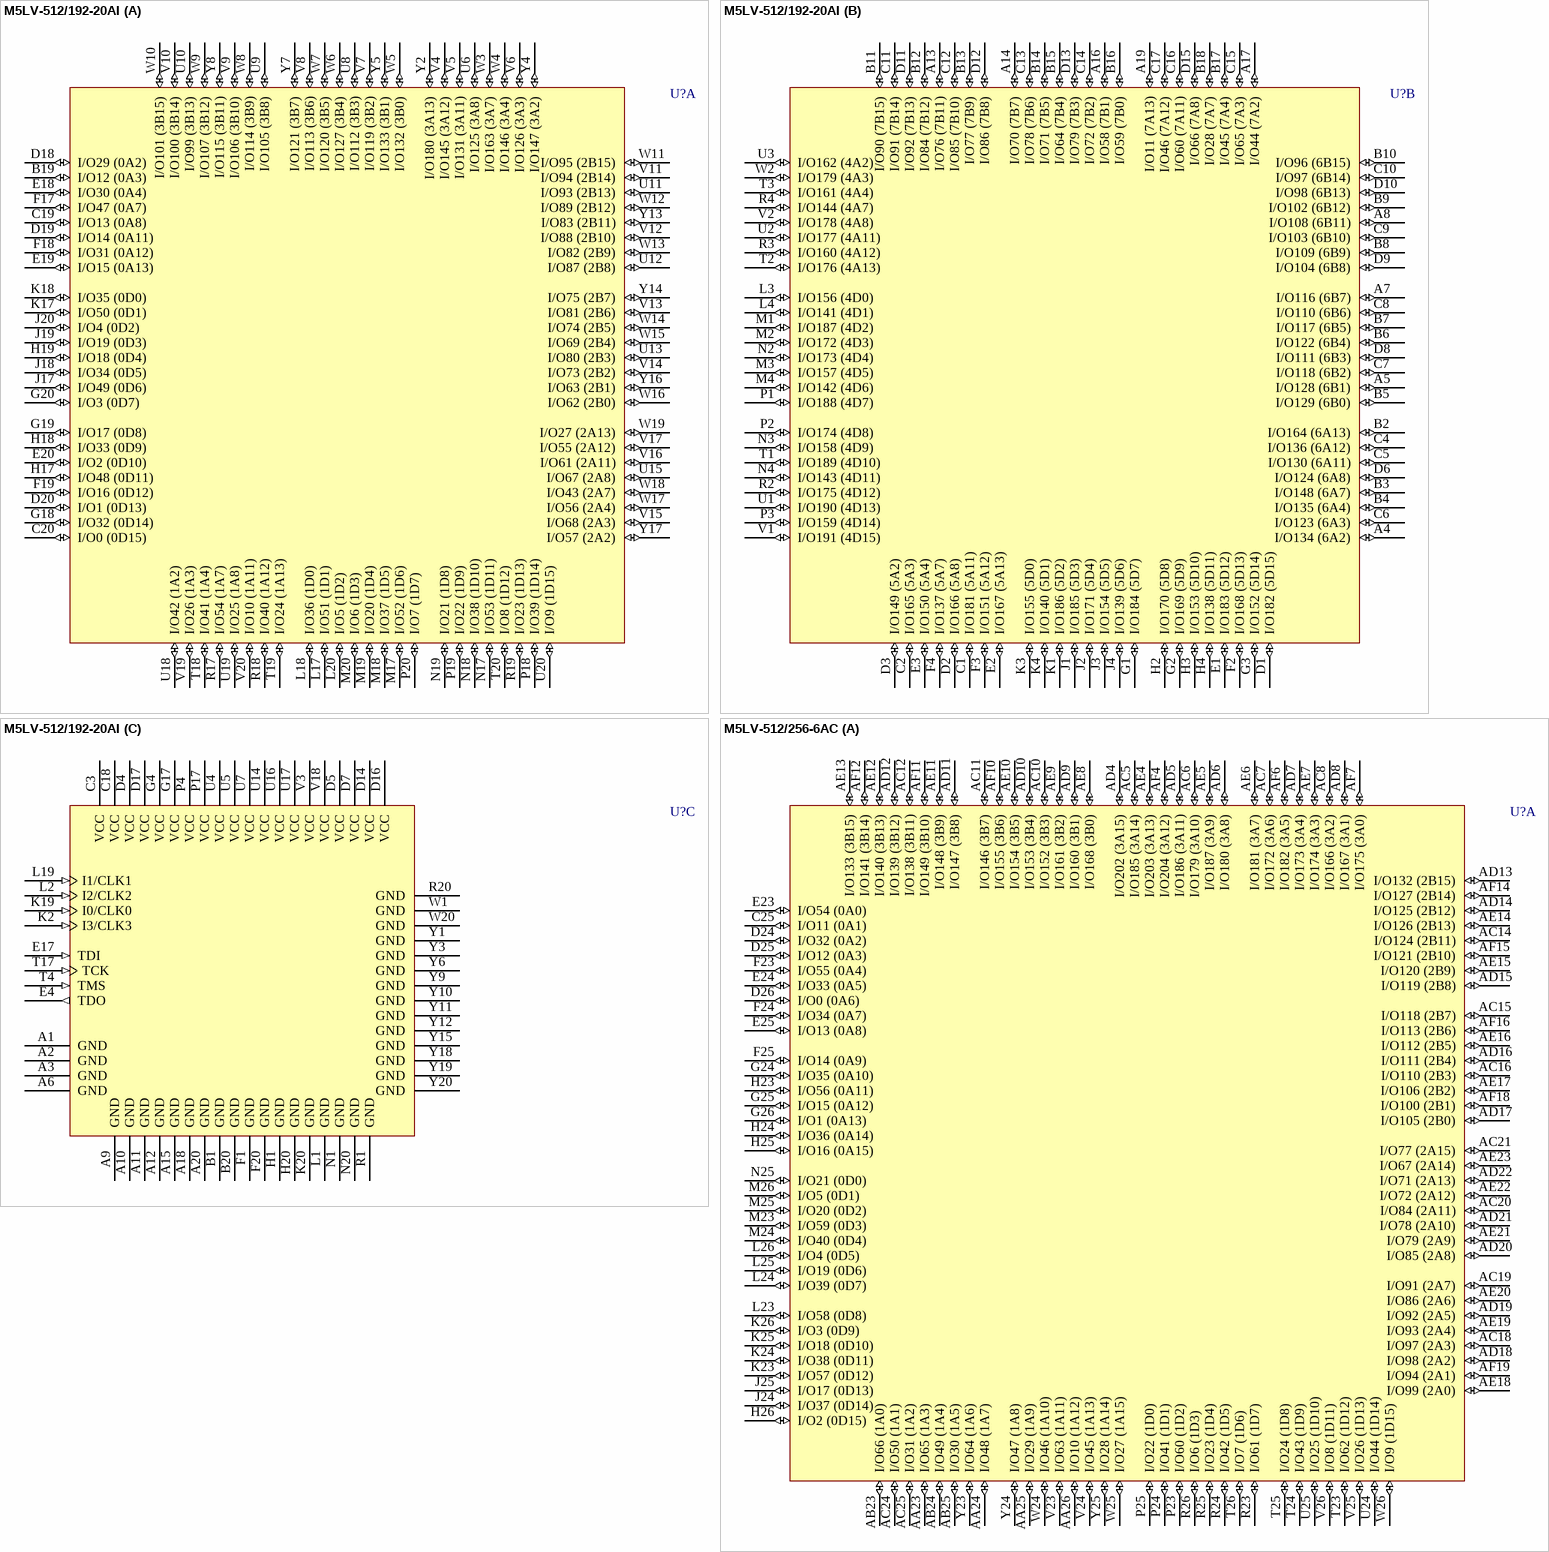
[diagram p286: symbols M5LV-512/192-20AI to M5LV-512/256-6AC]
